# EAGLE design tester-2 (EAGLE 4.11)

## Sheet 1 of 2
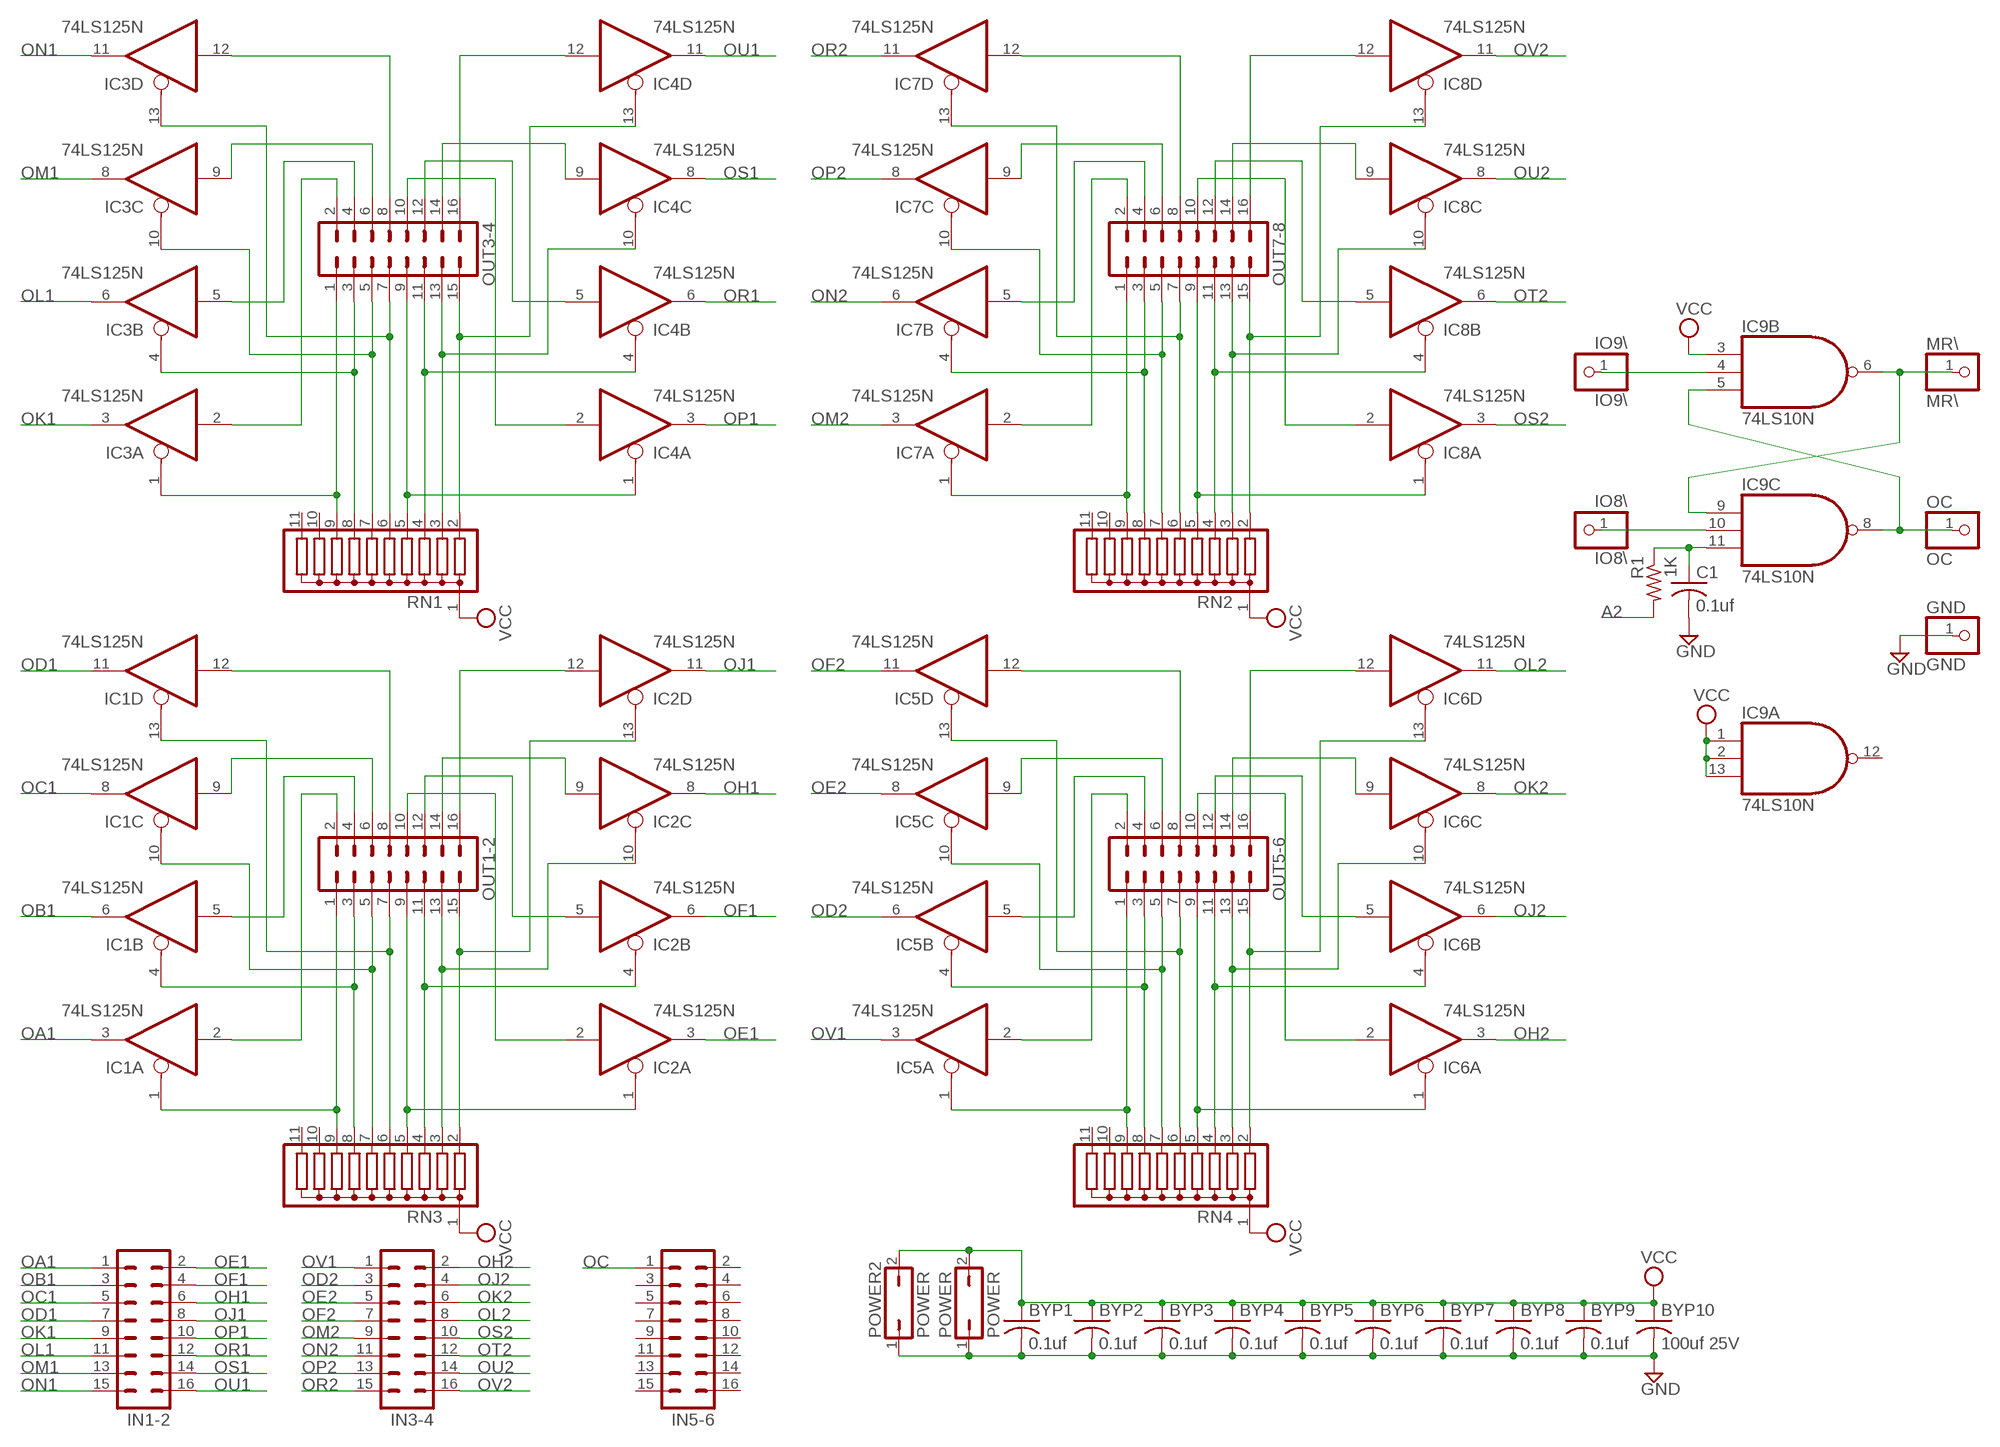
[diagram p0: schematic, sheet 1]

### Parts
BYP1  0.1uf  C-US050-025X075  [C050-025X075]
BYP2  0.1uf  C-US050-025X075  [C050-025X075]
BYP3  0.1uf  C-US050-025X075  [C050-025X075]
BYP4  0.1uf  C-US050-025X075  [C050-025X075]
BYP5  0.1uf  C-US050-025X075  [C050-025X075]
BYP6  0.1uf  C-US050-025X075  [C050-025X075]
BYP7  0.1uf  C-US050-025X075  [C050-025X075]
BYP8  0.1uf  C-US050-025X075  [C050-025X075]
BYP9  0.1uf  C-US050-025X075  [C050-025X075]
BYP10  100uf 25V  C-US150-064X183  [C150-064X183]
C1  0.1uf  C-US050-025X075  [C050-025X075]
GND  GND  PINHD-1X1  [1X01]
IC1  74LS125N  [DIL14]
IC2  74LS125N  [DIL14]
IC3  74LS125N  [DIL14]
IC4  74LS125N  [DIL14]
IC5  74LS125N  [DIL14]
IC6  74LS125N  [DIL14]
IC7  74LS125N  [DIL14]
IC8  74LS125N  [DIL14]
IC9  74LS10N  [DIL14]
IN1-2  MA08-2  [MA08-2]
IN3-4  MA08-2  [MA08-2]
IN5-6  MA08-2  [MA08-2]
IO8\  IO8\  PINHD-1X1  [1X01]
IO9\  IO9\  PINHD-1X1  [1X01]
MR\  MR\  PINHD-1X1  [1X01]
OC  OC  PINHD-1X1  [1X01]
OUT1-2  MA08-2  [MA08-2]
OUT3-4  MA08-2  [MA08-2]
OUT5-6  MA08-2  [MA08-2]
OUT7-8  MA08-2  [MA08-2]
POWER  POWER  JP1Q  [JP1]
POWER2  POWER  JP1Q  [JP1]
R1  1K  R-US_0207/10  [0207/10]
RN1  G10R  [SIL11]
RN2  G10R  [SIL11]
RN3  G10R  [SIL11]
RN4  G10R  [SIL11]

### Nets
A2: R1.2 ; also sheet 2
GND [Power]: BYP1.2 BYP2.2 BYP3.2 BYP4.2 BYP5.2 BYP6.2 BYP7.2 BYP8.2 BYP9.2 BYP10.2 C1.2 GND.1 POWER2.1 POWER.1 ; also sheet 2
IO8\: IC9.10(C:I1) IO8\.1
IO9\: IC9.4(B:I1) IO9\.1
MR\: IC9.6(B:O) IC9.9(C:I0) MR\.1
N$5: C1.1 IC9.11(C:I2) R1.1
N$53: IC1.1(A:OE) OUT1-2.1 RN3.9
N$54: IC1.4(B:OE) OUT1-2.3 RN3.8
N$55: IC1.10(C:OE) OUT1-2.5 RN3.7
N$56: IC1.13(D:OE) OUT1-2.7 RN3.6
N$57: IC1.2(A:I) OUT1-2.2
N$58: IC1.5(B:I) OUT1-2.4
N$59: IC1.9(C:I) OUT1-2.6
N$60: IC1.12(D:I) OUT1-2.8
N$61: IC5.4(B:OE) OUT5-6.3 RN4.8
N$62: IC2.10(C:OE) OUT1-2.13 RN3.3
N$63: IC2.4(B:OE) OUT1-2.11 RN3.4
N$64: IC2.1(A:OE) OUT1-2.9 RN3.5
N$65: IC2.2(A:I) OUT1-2.10
N$66: IC2.5(B:I) OUT1-2.12
N$67: IC2.9(C:I) OUT1-2.14
N$68: IC2.12(D:I) OUT1-2.16
N$138: IC5.13(D:OE) OUT5-6.7 RN4.6
N$139: IC2.13(D:OE) OUT1-2.15 RN3.2
N$140: IC5.2(A:I) OUT5-6.2
N$141: IC5.5(B:I) OUT5-6.4
N$142: IC5.9(C:I) OUT5-6.6
N$143: IC5.12(D:I) OUT5-6.8
N$144: IC6.10(C:OE) OUT5-6.13 RN4.3
N$145: IC6.4(B:OE) OUT5-6.11 RN4.4
N$146: IC6.1(A:OE) OUT5-6.9 RN4.5
N$147: IC6.2(A:I) OUT5-6.10
N$148: IC6.9(C:I) OUT5-6.14
N$149: IC6.12(D:I) OUT5-6.16
N$150: IC5.1(A:OE) OUT5-6.1 RN4.9
N$151: IC5.10(C:OE) OUT5-6.5 RN4.7
N$152: IC6.5(B:I) OUT5-6.12
N$153: IC6.13(D:OE) OUT5-6.15 RN4.2
N$154: IC3.4(B:OE) OUT3-4.3 RN1.8
N$155: IC3.13(D:OE) OUT3-4.7 RN1.6
N$156: IC3.2(A:I) OUT3-4.2
N$157: IC3.5(B:I) OUT3-4.4
N$158: IC3.9(C:I) OUT3-4.6
N$159: IC3.12(D:I) OUT3-4.8
N$160: IC4.10(C:OE) OUT3-4.13 RN1.3
N$161: IC4.4(B:OE) OUT3-4.11 RN1.4
N$162: IC4.1(A:OE) OUT3-4.9 RN1.5
N$163: IC4.2(A:I) OUT3-4.10
N$164: IC4.9(C:I) OUT3-4.14
N$165: IC4.12(D:I) OUT3-4.16
N$166: IC3.1(A:OE) OUT3-4.1 RN1.9
N$167: IC3.10(C:OE) OUT3-4.5 RN1.7
N$168: IC4.5(B:I) OUT3-4.12
N$169: IC4.13(D:OE) OUT3-4.15 RN1.2
N$170: IC7.4(B:OE) OUT7-8.3 RN2.8
N$171: IC7.13(D:OE) OUT7-8.7 RN2.6
N$172: IC7.2(A:I) OUT7-8.2
N$173: IC7.5(B:I) OUT7-8.4
N$174: IC7.9(C:I) OUT7-8.6
N$175: IC7.12(D:I) OUT7-8.8
N$176: IC8.10(C:OE) OUT7-8.13 RN2.3
N$177: IC8.4(B:OE) OUT7-8.11 RN2.4
N$178: IC8.1(A:OE) OUT7-8.9 RN2.5
N$179: IC8.2(A:I) OUT7-8.10
N$180: IC8.9(C:I) OUT7-8.14
N$181: IC8.12(D:I) OUT7-8.16
N$182: IC7.1(A:OE) OUT7-8.1 RN2.9
N$183: IC7.10(C:OE) OUT7-8.5 RN2.7
N$184: IC8.5(B:I) OUT7-8.12
N$185: IC8.13(D:OE) OUT7-8.15 RN2.2
OA1: IC1.3(A:O) IN1-2.1 ; also sheet 2
OB1: IC1.6(B:O) IN1-2.3 ; also sheet 2
OC: IC9.5(B:I2) IC9.8(C:O) IN5-6.1 OC.1
OC1: IC1.8(C:O) IN1-2.5 ; also sheet 2
OD1: IC1.11(D:O) IN1-2.7 ; also sheet 2
OD2: IC5.6(B:O) IN3-4.3 ; also sheet 2
OE1: IC2.3(A:O) IN1-2.2 ; also sheet 2
OE2: IC5.8(C:O) IN3-4.5 ; also sheet 2
OF1: IC2.6(B:O) IN1-2.4 ; also sheet 2
OF2: IC5.11(D:O) IN3-4.7 ; also sheet 2
OH1: IC2.8(C:O) IN1-2.6 ; also sheet 2
OH2: IC6.3(A:O) IN3-4.2 ; also sheet 2
OJ1: IC2.11(D:O) IN1-2.8 ; also sheet 2
OJ2: IC6.6(B:O) IN3-4.4 ; also sheet 2
OK1: IC3.3(A:O) IN1-2.9 ; also sheet 2
OK2: IC6.8(C:O) IN3-4.6 ; also sheet 2
OL1: IC3.6(B:O) IN1-2.11 ; also sheet 2
OL2: IC6.11(D:O) IN3-4.8 ; also sheet 2
OM1: IC3.8(C:O) IN1-2.13 ; also sheet 2
OM2: IC7.3(A:O) IN3-4.9 ; also sheet 2
ON1: IC3.11(D:O) IN1-2.15 ; also sheet 2
ON2: IC7.6(B:O) IN3-4.11 ; also sheet 2
OP1: IC4.3(A:O) IN1-2.10 ; also sheet 2
OP2: IC7.8(C:O) IN3-4.13 ; also sheet 2
OR1: IC4.6(B:O) IN1-2.12 ; also sheet 2
OR2: IC7.11(D:O) IN3-4.15 ; also sheet 2
OS1: IC4.8(C:O) IN1-2.14 ; also sheet 2
OS2: IC8.3(A:O) IN3-4.10 ; also sheet 2
OT2: IC8.6(B:O) IN3-4.12 ; also sheet 2
OU1: IC4.11(D:O) IN1-2.16 ; also sheet 2
OU2: IC8.8(C:O) IN3-4.14 ; also sheet 2
OV1: IC5.3(A:O) IN3-4.1 ; also sheet 2
OV2: IC8.11(D:O) IN3-4.16 ; also sheet 2
VCC [Power]: BYP1.1 BYP2.1 BYP3.1 BYP4.1 BYP5.1 BYP6.1 BYP7.1 BYP8.1 BYP9.1 BYP10.1 IC9.1(A:I0) IC9.2(A:I1) IC9.3(B:I0) IC9.13(A:I2) POWER2.2 POWER.2 RN1.1 RN2.1 RN3.1 RN4.1 ; also sheet 2
Unconnected: IC9.12(A:O) IN5-6.2 IN5-6.3 IN5-6.4 IN5-6.5 IN5-6.6 IN5-6.7 IN5-6.8 IN5-6.9 IN5-6.10 IN5-6.11 IN5-6.12 IN5-6.13 IN5-6.14 IN5-6.15 IN5-6.16 RN1.10 RN1.11 RN2.10 RN2.11 RN3.10 RN3.11 RN4.10 RN4.11

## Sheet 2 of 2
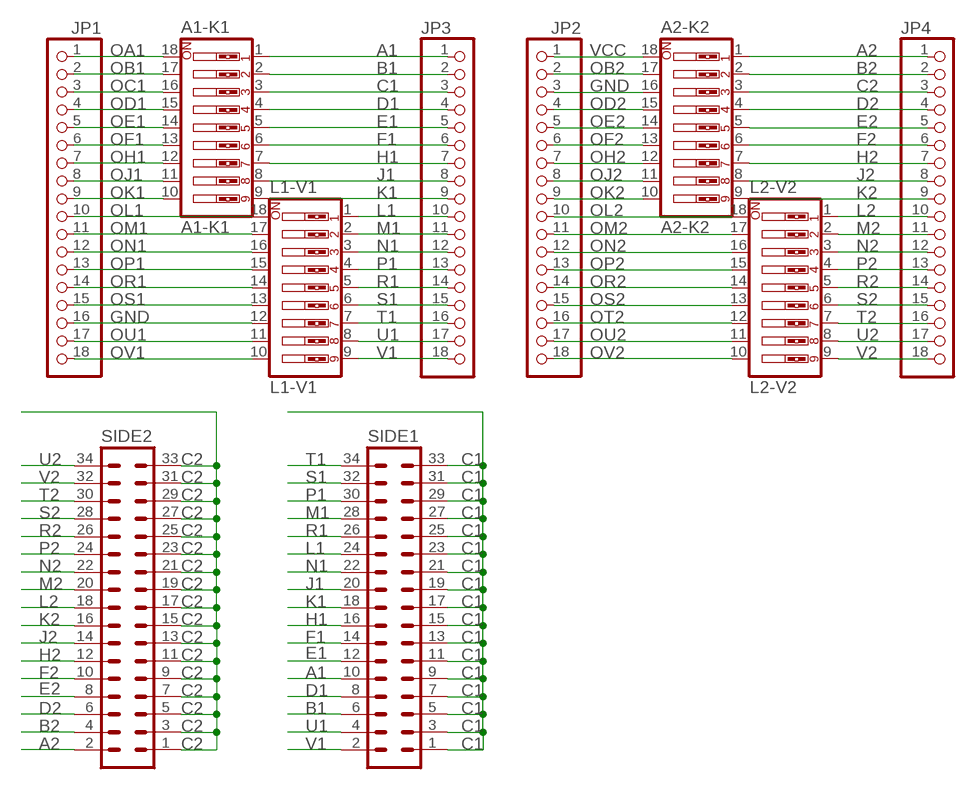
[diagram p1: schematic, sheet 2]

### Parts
A1-K1  A1-K1  SW_DIP-9  [EDG-09]
A2-K2  A2-K2  SW_DIP-9  [EDG-09]
JP1  PINHD-1X18  [1X18]
JP2  PINHD-1X18  [1X18]
JP3  PINHD-1X18  [1X18]
JP4  PINHD-1X18  [1X18]
L1-V1  L1-V1  SW_DIP-9  [EDG-09]
L2-V2  L2-V2  SW_DIP-9  [EDG-09]
SIDE1  MA17-2  [MA17-2]
SIDE2  MA17-2  [MA17-2]

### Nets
A1: A1-K1.1 JP3.1 SIDE1.10
A2: A2-K2.1 JP4.1 SIDE2.2 ; also sheet 1
B1: A1-K1.2 JP3.2 SIDE1.6
B2: A2-K2.2 JP4.2 SIDE2.4
C1: A1-K1.3 JP3.3 SIDE1.1 SIDE1.3 SIDE1.5 SIDE1.7 SIDE1.9 SIDE1.11 SIDE1.13 SIDE1.15 SIDE1.17 SIDE1.19 SIDE1.21 SIDE1.23 SIDE1.25 SIDE1.27 SIDE1.29 SIDE1.31 SIDE1.33
C2: A2-K2.3 JP4.3 SIDE2.1 SIDE2.3 SIDE2.5 SIDE2.7 SIDE2.9 SIDE2.11 SIDE2.13 SIDE2.15 SIDE2.17 SIDE2.19 SIDE2.21 SIDE2.23 SIDE2.25 SIDE2.27 SIDE2.29 SIDE2.31 SIDE2.33
D1: A1-K1.4 JP3.4 SIDE1.8
D2: A2-K2.4 JP4.4 SIDE2.6
E1: A1-K1.5 JP3.5 SIDE1.12
E2: A2-K2.5 JP4.5 SIDE2.8
F1: A1-K1.6 JP3.6 SIDE1.14
F2: A2-K2.6 JP4.6 SIDE2.10
GND [Power]: A2-K2.16 JP1.16 JP2.3 L1-V1.12 ; also sheet 1
H1: A1-K1.7 JP3.7 SIDE1.16
H2: A2-K2.7 JP4.7 SIDE2.12
J1: A1-K1.8 JP3.8 SIDE1.20
J2: A2-K2.8 JP4.8 SIDE2.14
K1: A1-K1.9 JP3.9 SIDE1.18
K2: A2-K2.9 JP4.9 SIDE2.16
L1: JP3.10 L1-V1.1 SIDE1.24
L2: JP4.10 L2-V2.1 SIDE2.18
M1: JP3.11 L1-V1.2 SIDE1.28
M2: JP4.11 L2-V2.2 SIDE2.20
N1: JP3.12 L1-V1.3 SIDE1.22
N2: JP4.12 L2-V2.3 SIDE2.22
OA1: A1-K1.18 JP1.1 ; also sheet 1
OB1: A1-K1.17 JP1.2 ; also sheet 1
OB2: A2-K2.17 JP2.2
OC1: A1-K1.16 JP1.3 ; also sheet 1
OD1: A1-K1.15 JP1.4 ; also sheet 1
OD2: A2-K2.15 JP2.4 ; also sheet 1
OE1: A1-K1.14 JP1.5 ; also sheet 1
OE2: A2-K2.14 JP2.5 ; also sheet 1
OF1: A1-K1.13 JP1.6 ; also sheet 1
OF2: A2-K2.13 JP2.6 ; also sheet 1
OH1: A1-K1.12 JP1.7 ; also sheet 1
OH2: A2-K2.12 JP2.7 ; also sheet 1
OJ1: A1-K1.11 JP1.8 ; also sheet 1
OJ2: A2-K2.11 JP2.8 ; also sheet 1
OK1: A1-K1.10 JP1.9 ; also sheet 1
OK2: A2-K2.10 JP2.9 ; also sheet 1
OL1: JP1.10 L1-V1.18 ; also sheet 1
OL2: JP2.10 L2-V2.18 ; also sheet 1
OM1: JP1.11 L1-V1.17 ; also sheet 1
OM2: JP2.11 L2-V2.17 ; also sheet 1
ON1: JP1.12 L1-V1.16 ; also sheet 1
ON2: JP2.12 L2-V2.16 ; also sheet 1
OP1: JP1.13 L1-V1.15 ; also sheet 1
OP2: JP2.13 L2-V2.15 ; also sheet 1
OR1: JP1.14 L1-V1.14 ; also sheet 1
OR2: JP2.14 L2-V2.14 ; also sheet 1
OS1: JP1.15 L1-V1.13 ; also sheet 1
OS2: JP2.15 L2-V2.13 ; also sheet 1
OT2: JP2.16 L2-V2.12 ; also sheet 1
OU1: JP1.17 L1-V1.11 ; also sheet 1
OU2: JP2.17 L2-V2.11 ; also sheet 1
OV1: JP1.18 L1-V1.10 ; also sheet 1
OV2: JP2.18 L2-V2.10 ; also sheet 1
P1: JP3.13 L1-V1.4 SIDE1.30
P2: JP4.13 L2-V2.4 SIDE2.24
R1: JP3.14 L1-V1.5 SIDE1.26
R2: JP4.14 L2-V2.5 SIDE2.26
S1: JP3.15 L1-V1.6 SIDE1.32
S2: JP4.15 L2-V2.6 SIDE2.28
T1: JP3.16 L1-V1.7 SIDE1.34
T2: JP4.16 L2-V2.7 SIDE2.30
U1: JP3.17 L1-V1.8 SIDE1.4
U2: JP4.17 L2-V2.8 SIDE2.34
V1: JP3.18 L1-V1.9 SIDE1.2
V2: JP4.18 L2-V2.9 SIDE2.32
VCC [Power]: A2-K2.18 JP2.1 ; also sheet 1

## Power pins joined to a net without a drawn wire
GND: IC1.7(P:GND) IC2.7(P:GND) IC3.7(P:GND) IC4.7(P:GND) IC5.7(P:GND) IC6.7(P:GND) IC7.7(P:GND) IC8.7(P:GND) IC9.7(P:GND)
VCC: IC1.14(P:VCC) IC2.14(P:VCC) IC3.14(P:VCC) IC4.14(P:VCC) IC5.14(P:VCC) IC6.14(P:VCC) IC7.14(P:VCC) IC8.14(P:VCC) IC9.14(P:VCC)

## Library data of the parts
A1-K1 A2-K2 L1-V1 L2-V2 = special:SW_DIP-9: DIP SWITCH
BYP1-BYP10 C1 = rcl:C-US: CAPACITOR, American symbol
GND IO8\ IO9\ MR\ OC = pinhead:PINHD-1X1: PIN HEADER
IC1-IC8 = 74xx-jameco:74*125: Quad bus BUFFER, 3-state
IC9 = 74xx-jameco:74*10: Triple 3-input NAND gate
IN1-2 IN3-4 IN5-6 OUT1-2 OUT3-4 OUT5-6 OUT7-8 = con-lstb:MA08-2: PIN HEADER
JP1-JP4 = pinhead:PINHD-1X18: PIN HEADER
POWER POWER2 = jumper:JP1Q: JUMPER
R1 = rcl:R-US_: RESISTOR, American symbol
RN1-RN4 = resistor-sil:G10R: SIL RESISTOR
SIDE1 SIDE2 = con-lstb:MA17-2: PIN HEADER

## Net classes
1 Power: width 0.305 mm, drill 0.305 mm

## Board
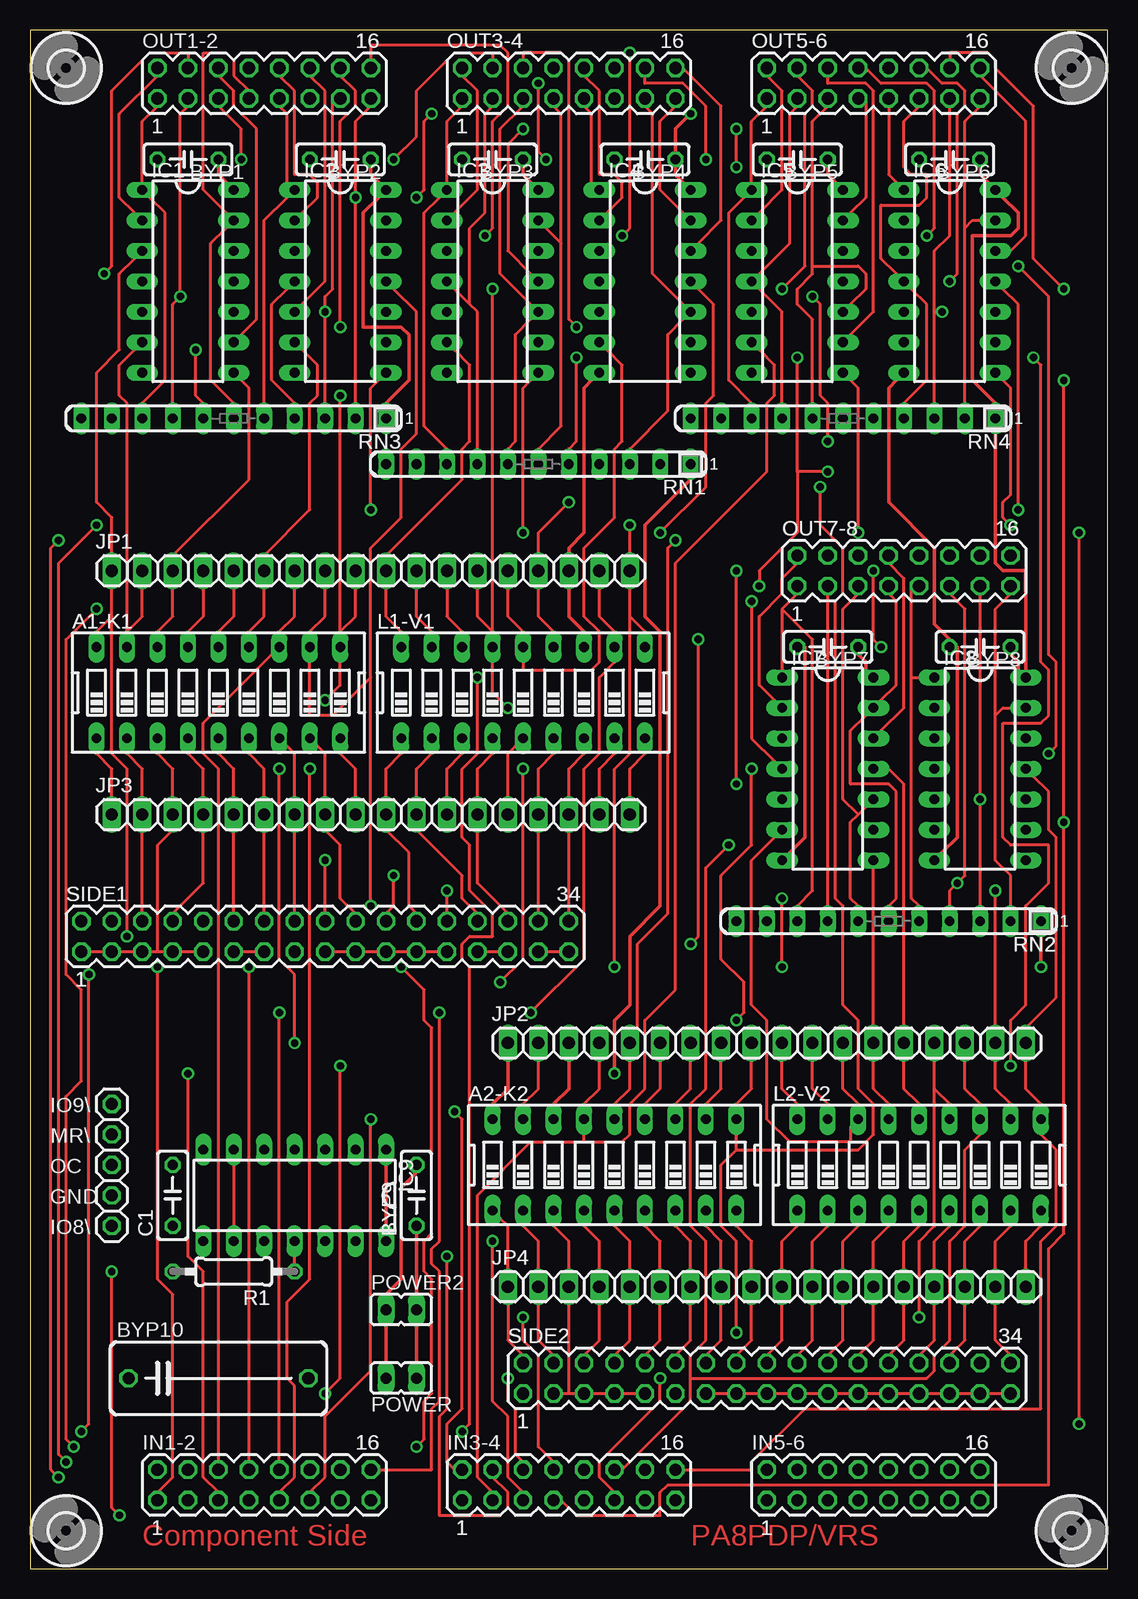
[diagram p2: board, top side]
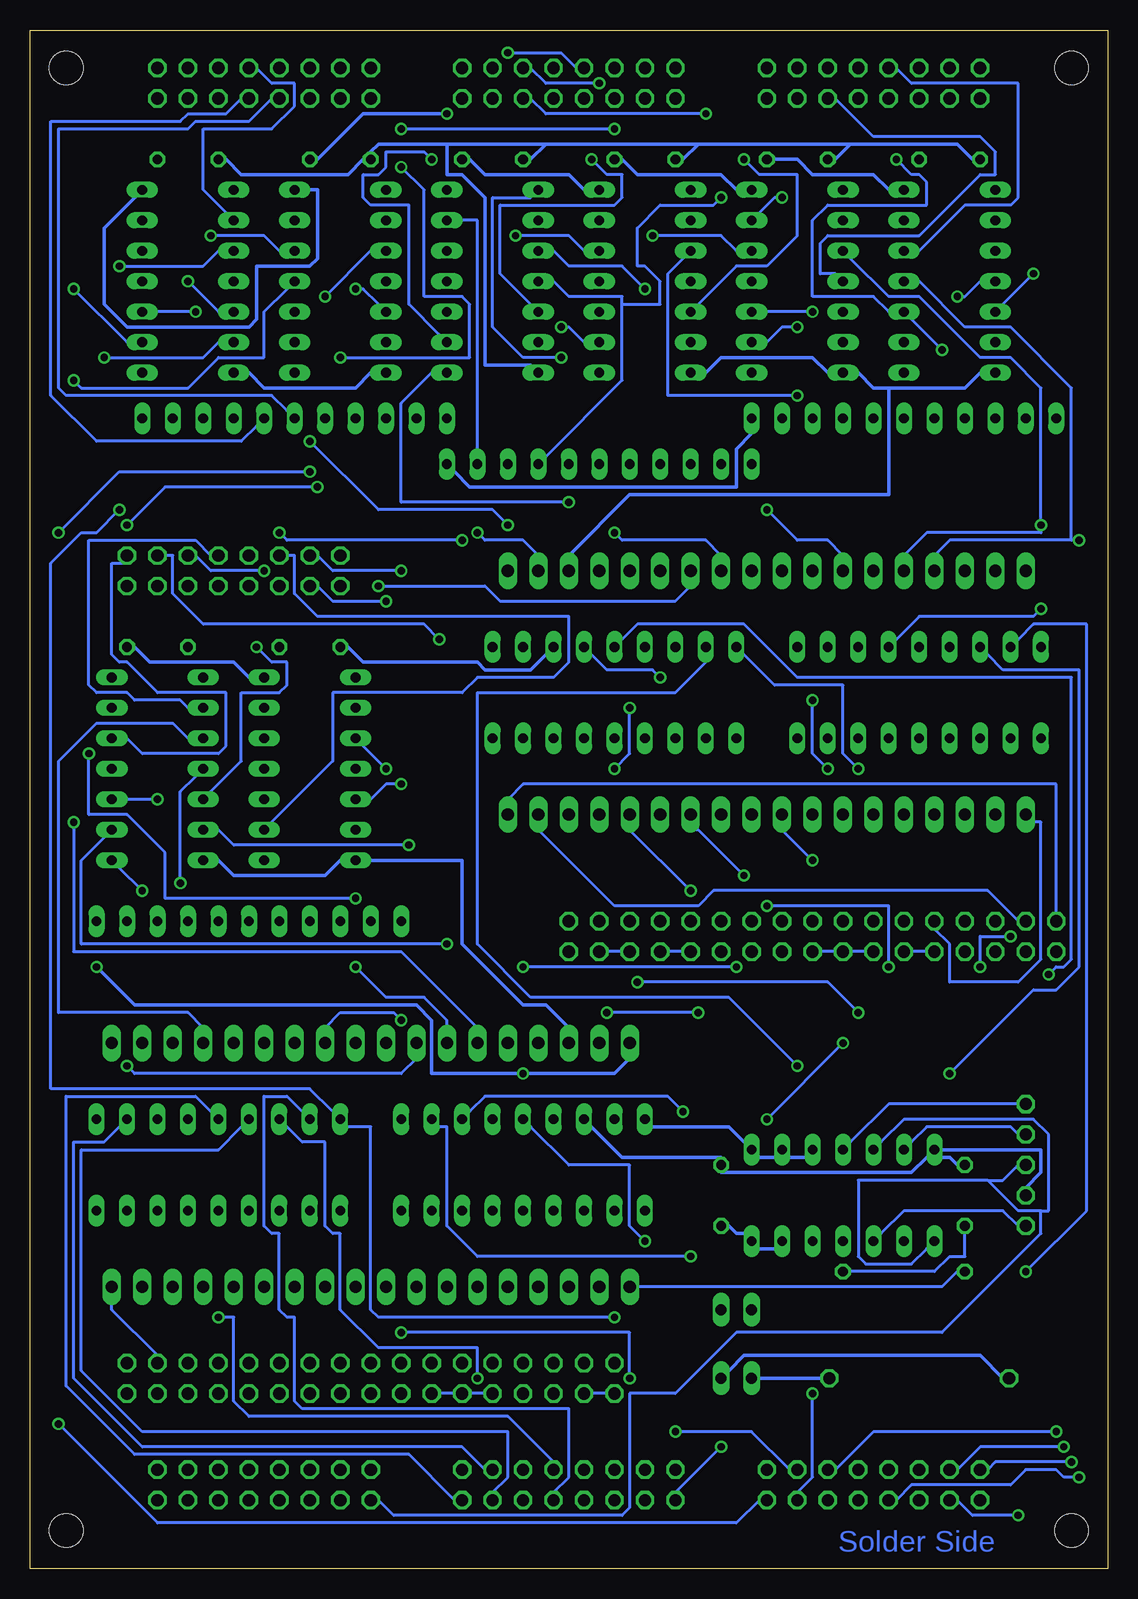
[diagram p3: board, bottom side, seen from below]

Size 89.84 x 128.25 mm. Coordinates in mm from the lower left corner, seen from the top.
Outline: 0,128.25 0,0 89.84,0 89.84,128.25 0,128.25
Copper layers (1*16): Top 0.035mm / dielectric 1.5mm / Bottom 0.035mm
Design rules "custompcb": minimum track width 10mil, minimum drill 24mil, track to track 12mil, track to pad 12mil, pad to pad 12mil, via to via 12mil, smd to smd 12mil, copper to edge 40mil, drill to drill 12mil, minimum pad ring 10mil, minimum via ring 8mil, stop-mask expansion 0mil, vias tented up to drill 0mil, thermal gap 10mil

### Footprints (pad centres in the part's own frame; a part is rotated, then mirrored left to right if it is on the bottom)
EDG-09 = drill 0.813 long: 1 -10.16,-3.81; 2 -7.62,-3.81; 3 -5.08,-3.81; 4 -2.54,-3.81; 5 0,-3.81; 6 2.54,-3.81; 7 5.08,-3.81; 8 7.62,-3.81; 9 10.16,-3.81; 10 10.16,3.81; 11 7.62,3.81; 12 5.08,3.81; 13 2.54,3.81; 14 0,3.81; 15 -2.54,3.81; 16 -5.08,3.81; 17 -7.62,3.81; 18 -10.16,3.81
C050-025X075 = drill 0.813 octagon: 1 -2.54,0; 2 2.54,0
C150-064X183 = drill 1.016 octagon: 1 -7.493,0; 2 7.493,0
1X01 = drill 1.016 octagon: 1 0,0
DIL14 = drill 0.813 long: 1 -7.62,-3.81; 2 -5.08,-3.81; 3 -2.54,-3.81; 4 0,-3.81; 5 2.54,-3.81; 6 5.08,-3.81; 7 7.62,-3.81; 8 7.62,3.81; 9 5.08,3.81; 10 2.54,3.81; 11 0,3.81; 12 -2.54,3.81; 13 -5.08,3.81; 14 -7.62,3.81
MA08-2 = drill 1.016 octagon: 1 -8.89,-1.27; 2 -8.89,1.27; 3 -6.35,-1.27; 4 -6.35,1.27; 5 -3.81,-1.27; 6 -3.81,1.27; 7 -1.27,-1.27; 8 -1.27,1.27; 9 1.27,-1.27; 10 1.27,1.27; 11 3.81,-1.27; 12 3.81,1.27; 13 6.35,-1.27; 14 6.35,1.27; 15 8.89,-1.27; 16 8.89,1.27
1X18 = drill 1.016 long: 1 -21.59,0; 2 -19.05,0; 3 -16.51,0; 4 -13.97,0; 5 -11.43,0; 6 -8.89,0; 7 -6.35,0; 8 -3.81,0; 9 -1.27,0; 10 1.27,0; 11 3.81,0; 12 6.35,0; 13 8.89,0; 14 11.43,0; 15 13.97,0; 16 16.51,0; 17 19.05,0; 18 21.59,0
JP1 = drill 0.914 long: 1 0,-1.27; 2 0,1.27
0207/10 = drill 0.813 octagon: 1 -5.08,0; 2 5.08,0
SIL11 = drill 0.813 long: 1 -12.7,0; 2 -10.16,0; 3 -7.62,0; 4 -5.08,0; 5 -2.54,0; 6 0,0; 7 2.54,0; 8 5.08,0; 9 7.62,0; 10 10.16,0; 11 12.7,0
MA17-2 = drill 1.016 octagon: 1 -20.32,-1.27; 2 -20.32,1.27; 3 -17.78,-1.27; 4 -17.78,1.27; 5 -15.24,-1.27; 6 -15.24,1.27; 7 -12.7,-1.27; 8 -12.7,1.27; 9 -10.16,-1.27; 10 -10.16,1.27; 11 -7.62,-1.27; 12 -7.62,1.27; 13 -5.08,-1.27; 14 -5.08,1.27; 15 -2.54,-1.27; 16 -2.54,1.27; 17 0,-1.27; 18 0,1.27; 19 2.54,-1.27; 20 2.54,1.27; 21 5.08,-1.27; 22 5.08,1.27; 23 7.62,-1.27; 24 7.62,1.27; 25 10.16,-1.27; 26 10.16,1.27; 27 12.7,-1.27; 28 12.7,1.27; 29 15.24,-1.27; 30 15.24,1.27; 31 17.78,-1.27; 32 17.78,1.27; 33 20.32,-1.27; 34 20.32,1.27
2,8 = hole 2.8: 0,0

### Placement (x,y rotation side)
A1-K1  15.71,73.01 0 top
A2-K2  48.73,33.64 0 top
BYP1  13.17,117.46 180 top
BYP2  25.87,117.46 180 top
BYP3  38.57,117.46 180 top
BYP4  51.27,117.46 180 top
BYP5  63.97,117.46 180 top
BYP6  76.67,117.46 180 top
BYP7  66.51,76.82 180 top
BYP8  79.21,76.82 180 top
BYP9  32.22,31.1 90 top
BYP10  15.71,15.86 0 top
C1  11.9,31.1 90 top
GND  6.82,31.1 90 top
IC1  13.17,107.3 270 top
IC2  25.87,107.3 270 top
IC3  38.57,107.3 270 top
IC4  51.27,107.3 270 top
IC5  63.97,107.3 270 top
IC6  76.67,107.3 270 top
IC7  66.51,66.66 270 top
IC8  79.21,66.66 270 top
IC9  22.06,31.1 180 top
IN1-2  19.52,6.97 0 top
IN3-4  44.92,6.97 0 top
IN5-6  70.32,6.97 0 top
IO8\  6.82,28.56 90 top
IO9\  6.82,38.72 90 top
JP1  28.41,83.17 0 top
JP2  61.43,43.8 0 top
JP3  28.41,62.85 0 top
JP4  61.43,23.48 0 top
L1-V1  41.11,73.01 0 top
L2-V2  74.13,33.64 0 top
MR\  6.82,36.18 90 top
OC  6.82,33.64 90 top
OUT1-2  19.52,123.81 0 top
OUT3-4  44.92,123.81 0 top
OUT5-6  70.32,123.81 0 top
OUT7-8  72.86,83.17 0 top
POWER  30.95,15.86 270 top
POWER2  30.95,21.57 270 top
R1  16.98,24.75 180 top
RN1  42.38,92.06 180 top
RN2  71.59,53.96 180 top
RN3  16.98,95.87 180 top
RN4  67.78,95.87 180 top
SIDE1  24.6,52.69 0 top
SIDE2  61.43,15.86 0 top
U$1  [2,8]  3.01,3.16 270 top
U$2  [2,8]  86.83,3.16 270 top
U$3  [2,8]  86.83,125.08 270 top
U$4  [2,8]  3.01,125.08 270 top

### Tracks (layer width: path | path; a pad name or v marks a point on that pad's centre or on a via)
A1
  Top 0.254: A1-K1.1 5.55,67.93 6.82,66.66 6.82,64.12 JP3.1
  Bottom 0.254: SIDE1.10 14.44,53.33 13.17,52.05 13.17,48.88 7.46,48.88 5.55,50.78 5.55,62.21 6.18,62.21 JP3.1
A2
  Top 0.254: A2-K2.1 39.2,29.2 39.84,28.56 39.84,24.75 JP4.1 39.84,22.21 39.84,19.04 41.11,17.77 SIDE2.2
  Bottom 0.254: R1.2 12.54,24.75 13.81,23.48 39.2,23.48 JP4.1
B1
  Top 0.254: A1-K1.2 8.09,67.93 9.36,66.66 9.36,64.12 JP3.2 9.36,61.58 9.36,54.59 SIDE1.6
B2
  Top 0.254: A2-K2.2 41.11,28.56 42.38,27.29 42.38,24.75 JP4.2 42.38,22.21 42.38,19.04 43.65,17.77 SIDE2.4
C1
  Top 0.254: A1-K1.3 10.63,67.93 11.9,66.66 11.9,64.12 JP3.3 11.9,61.58 10.63,60.31 10.63,51.42 | SIDE1.1 4.92,51.42 6.18,51.42 SIDE1.3 7.46,51.42 8.73,51.42 SIDE1.5 10,51.42 10.63,51.42 | 10.63,51.42 11.27,51.42 SIDE1.7 12.54,51.42 13.81,51.42 SIDE1.9 | SIDE1.13 18.89,51.42 17.62,51.42 SIDE1.11 | SIDE1.17 25.23,51.42 26.51,51.42 SIDE1.19 27.78,51.42 29.05,51.42 SIDE1.21 30.32,51.42 31.59,51.42 SIDE1.23 32.86,51.42 34.12,51.42 SIDE1.25 | SIDE1.29 39.2,51.42 37.94,51.42 SIDE1.27 | SIDE1.33 44.29,51.42 43.02,51.42 SIDE1.31
  Bottom 0.254: SIDE1.11 16.35,51.42 15.08,51.42 SIDE1.9 | SIDE1.13 20.16,51.42 21.43,51.42 SIDE1.15 22.7,51.42 23.96,51.42 SIDE1.17 | SIDE1.27 36.66,51.42 35.4,51.42 SIDE1.25 | SIDE1.31 41.74,51.42 40.48,51.42 SIDE1.29
C2
  Top 0.254: A2-K2.3 43.65,28.56 44.92,27.29 44.92,24.75 JP4.3 44.92,22.21 44.92,14.59 | 44.92,14.59 44.29,14.59 SIDE2.3 | 44.92,14.59 45.55,14.59 SIDE2.5 46.83,14.59 48.09,14.59 SIDE2.7 49.37,14.59 50.63,14.59 SIDE2.9 | SIDE2.13 56.98,14.59 58.26,14.59 SIDE2.15 59.52,14.59 60.8,14.59 SIDE2.17 62.06,14.59 63.34,14.59 SIDE2.19 64.6,14.59 65.88,14.59 SIDE2.21 67.14,14.59 68.41,14.59 SIDE2.23 69.68,14.59 70.95,14.59 SIDE2.25 72.22,14.59 73.49,14.59 SIDE2.27 74.77,14.59 76.03,14.59 SIDE2.29 77.3,14.59 78.57,14.59 SIDE2.31 79.84,14.59 81.11,14.59 SIDE2.33
  Bottom 0.254: SIDE2.1 41.74,14.59 43.02,14.59 SIDE2.3 | SIDE2.9 51.91,14.59 53.18,14.59 SIDE2.11 54.45,14.59 55.72,14.59 SIDE2.13
D1
  Top 0.254: A1-K1.4 13.17,67.93 14.44,66.66 14.44,64.12 JP3.4 14.44,61.58 14.44,57.13 11.9,54.59 SIDE1.8
D2
  Top 0.254: A2-K2.4 46.19,28.56 47.46,27.29 47.46,24.75 JP4.4 47.46,22.21 47.46,19.04 46.19,17.77 SIDE2.6
E1
  Top 0.254: A1-K1.5 15.71,67.93 16.98,66.66 16.98,64.12 JP3.5 16.98,61.58 16.98,54.59 SIDE1.12
E2
  Top 0.254: A2-K2.5 48.73,28.56 50,27.29 50,24.75 JP4.5 50,22.21 50,19.04 48.73,17.77 SIDE2.8
F1
  Top 0.254: A1-K1.6 18.25,67.93 19.52,66.66 19.52,64.12 JP3.6 19.52,61.58 19.52,54.59 SIDE1.14
F2
  Top 0.254: A2-K2.6 51.27,28.56 52.54,27.29 52.54,24.75 JP4.6 52.54,22.21 52.54,19.04 51.27,17.77 SIDE2.10
GND
  Top 0.305: A2-K2.16 43.65,38.72 44.92,39.99 44.92,42.53 JP2.3 | BYP9.2 32.22,33.01 30.95,31.73 30.95,24.11 29.68,22.84 POWER2.1 29.68,20.3 29.68,17.13 POWER.1 | IC7.7 63.34,59.67 64.6,60.95 64.6,76.82 BYP7.2 | IC8.7 76.03,59.67 77.3,60.95 77.3,76.82 BYP8.2 76.67,77.45 75.4,78.72 75.4,85.08 71.59,88.89 71.59,98.41 72.22,99.05 IC6.7 | L1-V1.12 46.19,78.09 44.92,79.36 44.92,81.9 JP1.16 44.92,84.44 44.92,85.08 46.19,86.34 46.19,98.41 46.83,99.05 IC4.7
  Bottom 0.305: C1.2 12.54,33.64 13.17,34.27 13.81,34.27 IC9.7 | GND.1 6.82,31.73 5.55,33.01 5.55,34.91 13.81,34.91 IC9.7 | BYP10.2 23.33,15.86 29.05,15.86 POWER.1 | A2-K2.16 43.02,36.81 40.48,34.27 32.22,34.27 BYP9.2 32.22,33.01 16.35,33.01 15.08,34.27 IC9.7 | 21.43,118.73 12.54,118.73 11.27,117.46 BYP1.2 | 21.43,118.73 22.7,117.46 BYP2.2 | 34.12,118.73 35.4,117.46 BYP3.2 | 34.12,118.73 21.43,118.73 | 46.83,118.73 48.09,117.46 BYP4.2 | 46.83,118.73 34.12,118.73 | 55.08,118.73 46.83,118.73 | 55.08,118.73 60.8,118.73 61.43,118.09 BYP5.2 62.06,117.46 63.34,116.19 72.22,116.19 73.49,117.46 BYP6.2 | IC5.7 61.43,99.68 62.7,98.41 70.32,98.41 71.59,99.68 IC6.7 | IC8.7 74.13,59.04 72.86,57.77 65.24,57.77 63.97,59.04 IC7.7 61.43,59.04 53.81,59.04 53.81,52.05 48.73,46.98 46.83,46.98 44.92,45.07 JP2.3 | 18.25,98.41 19.52,98.41 20.79,99.68 IC2.7 23.33,99.68 24.6,100.95 32.22,100.95 33.49,99.68 IC3.7 | 18.25,98.41 11.9,98.41 10.63,99.68 IC1.7 | 18.25,98.41 18.25,89.52 39.84,89.52 44.92,84.44 JP1.16 | BYP7.2 63.34,76.82 62.06,75.55 52.54,75.55 51.91,74.92 48.09,74.92 46.83,76.19 L1-V1.12 | 55.08,118.73 55.08,116.19 53.81,116.19 51.91,114.28 51.91,100.31 48.09,100.31 IC4.7
H1
  Top 0.254: A1-K1.7 21.43,68.56 22.06,67.93 22.06,64.12 JP3.7 22.06,61.58 22.06,54.59 SIDE1.16
H2
  Top 0.254: A2-K2.7 53.81,28.56 55.08,27.29 55.08,24.75 JP4.7 55.08,22.21 55.08,19.04 53.81,17.77 SIDE2.12
IO8\
  Bottom 0.254: IC9.10 18.89,27.93 16.98,29.83 8.73,29.83 7.46,28.56 IO8\.1
IO9\
  Bottom 0.254: IC9.4 21.43,35.55 18.25,38.72 7.46,38.72 IO9\.1
J1
  Top 0.254: A1-K1.8 23.96,68.56 24.6,67.93 24.6,64.12 JP3.8 24.6,61.58 25.87,60.31 25.87,55.87 27.14,54.59 SIDE1.20
J2
  Top 0.254: A2-K2.8 56.35,28.56 57.62,27.29 57.62,24.75 JP4.8 57.62,22.21 57.62,19.04 56.35,17.77 SIDE2.14
K1  (via drill 0.61)
  Top 0.254: A1-K1.9 25.87,67.93 27.14,66.66 27.14,64.12 JP3.9 | v24.6,59.04 24.6,54.59 SIDE1.18
  Bottom 0.254: v24.6,59.04 27.14,61.58 JP3.9
K2
  Top 0.254: A2-K2.9 58.89,28.56 60.16,27.29 60.16,24.75 JP4.9 60.16,22.21 60.16,19.04 58.89,17.77 SIDE2.16
L1
  Top 0.254: L1-V1.1 30.95,67.93 29.68,66.66 29.68,64.12 JP3.10 29.68,61.58 31.59,59.67 31.59,55.23 32.22,54.59 SIDE1.24
L2
  Top 0.254: L2-V2.1 63.97,28.56 62.7,27.29 62.7,24.75 JP4.10 62.7,22.21 62.7,19.04 61.43,17.77 SIDE2.18
M1
  Top 0.254: L1-V1.2 33.49,67.93 32.22,66.66 32.22,64.12 JP3.11 32.22,61.58 36.03,57.77 36.03,55.87 37.3,54.59 SIDE1.28
M2
  Top 0.254: L2-V2.2 66.51,28.56 65.24,27.29 65.24,24.75 JP4.11 65.24,22.21 65.24,19.04 63.97,17.77 SIDE2.20
MR\
  Top 0.254: IC9.9 16.98,28.56 16.98,33.64 IC9.6
  Bottom 0.254: MR\.1 7.46,36.18 8.09,36.81 15.08,36.81 16.35,35.55 IC9.6
N1  (via drill 0.61)
  Top 0.254: L1-V1.3 36.03,67.93 34.76,66.66 34.76,64.12 JP3.12 | v30.32,57.77 30.32,55.23 29.68,54.59 SIDE1.22
  Bottom 0.254: v30.32,57.77 34.12,61.58 34.76,61.58 JP3.12
N2
  Top 0.254: L2-V2.3 69.05,28.56 67.78,27.29 67.78,24.75 JP4.12 67.78,22.21 67.78,19.04 66.51,17.77 SIDE2.22
N$5
  Top 0.254: R1.1 22.06,25.38 22.06,26.02 IC9.11
  Bottom 0.254: C1.1 11.9,27.93 11.9,26.02 13.17,26.02 14.44,24.75 21.43,24.75 R1.1
N$53
  Top 0.254: RN3.9 9.36,97.14 11.27,99.05 11.27,113.02 10,114.28 IC1.1 9.36,115.55 9.36,120.64 10.63,121.91 OUT1-2.1
N$54  (via drill 0.61)
  Top 0.254: RN3.8 11.9,97.14 11.9,105.39 v12.54,106.03 12.54,121.27 13.17,121.91 OUT1-2.3
  Bottom 0.254: v12.54,106.03 11.9,106.03 10.63,107.3 IC1.4
N$55  (via drill 0.61)
  Top 0.254: v13.81,101.58 13.81,97.78 14.44,97.14 RN3.7 | v17.62,117.46 17.62,120 15.71,121.91 OUT1-2.5
  Bottom 0.254: v13.81,101.58 16.35,104.12 IC1.10 18.25,104.76 19.52,106.03 24.6,106.03 24.6,112.38 23.33,113.65 15.08,113.65 15.08,115.55 15.71,116.19 16.35,116.19 v17.62,117.46
N$56
  Top 0.254: RN3.6 16.98,97.14 15.08,99.05 15.08,110.47 16.35,111.75 IC1.13 16.35,113.02 14.44,114.92 14.44,126.35 16.35,126.35 16.98,125.72 16.98,124.44 18.25,123.17 OUT1-2.7
N$57
  Top 0.254: IC1.2 8.73,113.02 7.46,114.28 7.46,121.27 10.63,124.44 OUT1-2.2
N$58  (via drill 0.61)
  Top 0.254: v6.18,107.94 6.82,108.57 6.82,123.17 10,126.35 13.17,126.35 13.17,125.72 OUT1-2.4
  Bottom 0.254: v6.18,107.94 8.73,105.39 IC1.5
N$59
  Top 0.254: IC1.9 17.62,102.86 18.89,104.12 18.89,120 16.98,121.91 16.98,123.17 15.71,124.44 OUT1-2.6
N$60
  Bottom 0.254: IC1.12 15.71,109.84 11.9,113.65 8.09,113.65 7.46,114.28 7.46,123.81 16.35,123.81 17.62,125.08 OUT1-2.8
N$61
  Top 0.254: RN4.8 62.7,97.14 62.7,104.76 60.8,106.67 IC5.4 60.8,107.94 63.34,110.47 63.34,121.27 63.97,121.91 OUT5-6.3
N$62  (via drill 0.61)
  Top 0.254: RN3.3 24.6,97.14 v24.6,104.76 24.6,106.03 25.23,106.67 25.23,122.54 OUT1-2.13
  Bottom 0.254: v24.6,104.76 28.41,104.76 IC2.10
N$63
  Top 0.254: RN3.4 22.06,97.14 20.16,99.05 20.16,105.39 21.43,106.67 IC2.4
  Bottom 0.254: OUT1-2.11 22.7,122.54 19.52,119.36 10.63,119.36 9.36,118.09 9.36,116.19 10.63,116.19 15.71,111.11 23.33,111.11 23.96,110.47 23.96,107.94 22.7,107.94 IC2.4
N$64
  Top 0.254: RN3.5 19.52,97.14 19.52,112.38 21.43,114.28 IC2.1 21.43,115.55 21.43,121.27 20.79,121.91 OUT1-2.9
N$65
  Top 0.254: IC2.2 22.7,113.02 23.96,114.28 23.96,115.55 23.33,116.19 22.06,116.19 22.06,123.17 20.79,124.44 OUT1-2.10
N$66
  Top 0.254: IC2.5 22.7,105.39 24.6,107.3 24.6,123.17 23.33,124.44 OUT1-2.12
N$67  (via drill 0.61)
  Top 0.254: v25.87,103.49 25.87,120.64 27.14,121.91 27.14,123.17 25.87,124.44 OUT1-2.14
  Bottom 0.254: v25.87,103.49 27.14,103.49 28.41,102.22 IC2.9
N$68  (via drill 0.61)
  Top 0.254: v37.94,111.11 38.57,111.75 38.57,120.64 39.84,121.91 39.84,126.35 39.2,126.98 28.41,126.98 28.41,125.72 OUT1-2.16
  Bottom 0.254: v37.94,111.11 32.22,111.11 30.95,109.84 IC2.12
N$138
  Top 0.254: IC5.13 68.41,113.02 69.68,114.28 69.68,122.54 OUT5-6.7
  Bottom 0.254: RN4.6 68.41,96.5 69.68,97.78 86.83,97.78 87.46,98.41 87.46,120 76.67,120 76.03,120.64 71.59,120.64 69.68,122.54 OUT5-6.7
N$139  (via drill 0.61)
  Top 0.254: RN3.2 27.14,97.14 v27.14,114.28 27.14,120.64 28.41,121.91 OUT1-2.15
  Bottom 0.254: v27.14,114.28 27.78,114.28 29.05,113.02 IC2.13
N$140
  Top 0.254: IC5.2 60.8,113.02 62.7,114.92 62.7,123.17 61.43,124.44 OUT5-6.2
N$141  (via drill 0.61)
  Top 0.254: v62.7,106.67 64.6,108.57 64.6,121.27 65.24,121.91 65.24,123.17 63.97,124.44 OUT5-6.4
  Bottom 0.254: v62.7,106.67 62.06,106.67 60.8,105.39 IC5.5
N$142
  Top 0.254: IC5.9 68.41,102.86 70.32,104.76 70.32,123.17 69.68,123.81 66.51,123.81 66.51,124.44 OUT5-6.6
N$143  (via drill 0.61)
  Top 0.254: v74.77,111.11 75.4,111.75 75.4,123.17 74.77,123.81 70.95,123.81 69.68,125.08 OUT5-6.8
  Bottom 0.254: v74.77,111.11 70.32,111.11 69.05,109.84 IC5.12
N$144  (via drill 0.61)
  Top 0.254: 75.4,104.76 75.4,109.84 76.67,111.11 76.67,121.91 OUT5-6.13 | 75.4,104.76 75.4,97.14 RN4.3 | 75.4,104.76 v76.03,104.76
  Bottom 0.254: v76.03,104.76 79.21,104.76 IC6.10
N$145
  Top 0.254: RN4.4 72.86,97.14 74.77,99.05 74.77,105.39 73.49,106.67 IC6.4 72.22,107.94 70.95,109.2 70.95,113.65 74.13,113.65 74.77,114.28 74.77,116.19 73.49,116.19 72.86,116.83 72.86,120.64 74.13,121.91 OUT5-6.11
N$146
  Top 0.254: IC6.1 72.22,115.55 71.59,116.19 71.59,121.91 OUT5-6.9
  Bottom 0.254: RN4.5 70.95,95.23 72.22,93.97 84.29,93.97 88.1,97.78 88.1,120.64 77.3,120.64 76.67,121.27 73.49,121.27 72.22,122.54 OUT5-6.9
N$147
  Bottom 0.254: IC6.2 73.49,113.02 75.4,114.92 75.4,120 69.68,120 67.78,121.91 67.78,123.81 69.68,123.81 70.95,125.08 OUT5-6.10
N$148  (via drill 0.61)
  Top 0.254: v86.19,106.67 83.65,109.2 83.65,121.91 80.48,125.08 80.48,125.72 79.84,126.35 76.67,126.35 76.67,125.72 OUT5-6.14
  Bottom 0.254: v86.19,106.67 81.75,102.22 IC6.9
N$149
  Top 0.254: IC6.12 81.75,109.84 83.02,111.11 83.02,120.64 79.21,124.44 OUT5-6.16
N$150
  Top 0.254: RN4.9 60.16,97.14 58.26,99.05 58.26,113.02 59.52,114.28 IC5.1 60.16,115.55 60.16,120.64 61.43,121.91 OUT5-6.1
N$151
  Top 0.254: 65.24,108.57 65.24,120.64 66.51,121.91 OUT5-6.5 | 65.24,108.57 65.24,107.94 63.97,106.67 63.97,105.39 65.24,104.12 65.24,97.14 RN4.7 | 65.24,108.57 69.05,108.57 69.68,107.94 69.68,106.67 68.41,105.39 IC5.10
N$152  (via drill 0.61)
  Top 0.254: v76.67,107.3 77.3,107.94 77.3,121.27 77.94,121.91 77.94,123.17 77.3,123.81 76.03,123.81 74.77,125.08 OUT5-6.12
  Bottom 0.254: v76.67,107.3 74.13,104.76 IC6.5
N$153
  Top 0.254: 77.94,111.75 77.94,97.14 RN4.2 | 77.94,111.75 78.57,112.38 79.21,112.38 IC6.13 | 77.94,111.75 77.94,120.64 79.21,121.91 OUT5-6.15
N$154
  Top 0.254: 36.66,105.39 35.4,106.67 IC3.4 | 36.66,105.39 37.3,104.76 37.3,93.33 RN1.8 | 36.66,105.39 36.66,111.75 37.94,113.02 37.94,121.27 38.57,121.91 OUT3-4.3
N$155
  Top 0.254: 44.29,110.47 44.29,95.23 42.38,93.33 RN1.6 | 44.29,110.47 43.02,111.75 IC3.13 | 44.29,110.47 44.29,121.27 43.65,121.91 OUT3-4.7
N$156
  Top 0.254: IC3.2 35.4,113.02 37.3,114.92 37.3,123.17 36.03,124.44 OUT3-4.2
N$157  (via drill 0.61)
  Top 0.254: v30.32,117.46 32.22,119.36 32.22,123.17 35.4,126.35 38.57,126.35 38.57,125.72 OUT3-4.4
  Bottom 0.254: v30.32,117.46 29.05,116.19 25.87,116.19 25.87,111.11 28.41,108.57 30.95,108.57 34.12,105.39 IC3.5
N$158  (via drill 0.61)
  Top 0.254: v45.55,103.49 44.92,104.12 44.92,125.72 44.29,126.35 41.11,126.35 41.11,125.72 OUT3-4.6
  Bottom 0.254: v45.55,103.49 44.92,103.49 43.65,102.22 IC3.9
N$159  (via drill 0.61)
  Top 0.254: v49.37,111.11 50,111.75 v50,126.35
  Bottom 0.254: v49.37,111.11 44.92,111.11 43.65,109.84 IC3.12 | v50,126.35 45.55,126.35 44.29,125.08 OUT3-4.8
N$160
  Top 0.254: RN1.3 50,93.33 53.18,96.5 53.18,102.86 54.45,104.12 IC4.10 54.45,105.39 51.91,107.94 51.91,121.27 51.27,121.91 OUT3-4.13
N$161  (via drill 0.61)
  Top 0.254: v33.49,121.27 32.86,120.64 32.86,114.92 v32.22,114.28
  Bottom 0.254: 40.48,105.39 40.48,106.03 44.92,106.03 46.19,107.3 IC4.4 | 40.48,105.39 40.48,99.05 46.83,92.69 RN1.4 | v33.49,121.27 46.83,121.27 48.09,122.54 OUT3-4.11 | v32.22,114.28 32.86,113.65 37.3,113.65 39.2,111.75 39.2,108.57 38.57,108.57 37.3,107.3 37.3,105.39 40.48,105.39
N$162  (via drill 0.61)
  Top 0.254: v45.55,100.95 45.55,93.97 44.92,93.33 RN1.5 | OUT3-4.9 46.19,121.91 46.83,121.27 46.83,115.55 IC4.1
  Bottom 0.254: v45.55,100.95 48.73,100.95 51.27,103.49 51.27,114.28 48.09,114.28 IC4.1
N$163
  Top 0.254: IC4.2 48.09,113.02 49.37,114.28 49.37,115.55 48.73,116.19 47.46,116.19 47.46,123.17 46.19,124.44 OUT3-4.10
N$164  (via drill 0.61)
  Top 0.254: v56.35,117.46 56.35,121.91 54.45,123.81 51.27,123.81 51.27,124.44 OUT3-4.14
  Bottom 0.254: v56.35,117.46 56.98,118.09 60.16,118.09 60.16,116.83 60.8,116.19 62.06,116.19 62.06,114.28 61.43,113.65 58.26,113.65 58.26,105.39 55.72,102.86 IC4.9
N$165
  Top 0.254: IC4.12 55.72,110.47 57.62,112.38 57.62,121.91 54.45,125.08 OUT3-4.16
N$166
  Top 0.254: RN1.9 34.76,93.33 32.86,95.23 32.86,113.02 34.12,114.28 IC3.1 34.76,115.55 34.76,120.64 36.03,121.91 OUT3-4.1
N$167
  Top 0.254: RN1.7 39.84,93.33 40.48,93.97 40.48,102.86 41.74,104.12 IC3.10 41.74,105.39 39.2,107.94 39.2,120 41.11,121.91 OUT3-4.5
N$168  (via drill 0.61)
  Top 0.254: v43.02,117.46 42.38,118.09 v42.38,123.81
  Bottom 0.254: v43.02,117.46 41.74,116.19 40.48,116.19 40.48,114.28 41.11,113.65 50.63,113.65 50.63,107.94 48.09,105.39 IC4.5 | v42.38,123.81 46.83,123.81 48.09,125.08 OUT3-4.12
N$169
  Top 0.254: OUT3-4.15 53.81,121.91 52.54,120.64 52.54,114.92 54.45,113.02 IC4.13
  Bottom 0.254: RN1.2 52.54,93.33 52.54,112.38 53.81,112.38 IC4.13
N$170  (via drill 0.61)
  Top 0.254: v60.16,80.63 60.16,69.2 62.06,67.3 IC7.4 | RN2.8 66.51,55.23 66.51,81.27 OUT7-8.3
  Bottom 0.254: v60.16,80.63 64.6,80.63 65.88,81.9 OUT7-8.3
N$171
  Top 0.254: RN2.6 71.59,55.23 72.22,55.87 72.22,64.75 71.59,65.39 68.41,65.39 68.41,69.83 69.68,71.11 IC7.13 70.95,72.38 72.22,73.64 72.22,80.63 71.59,81.27 OUT7-8.7
N$172
  Top 0.254: IC7.2 62.06,72.38 60.8,73.64 60.8,79.36 62.7,81.27 62.7,82.53 63.97,83.8 OUT7-8.2
N$173  (via drill 0.61)
  Top 0.254: v58.89,65.39 v58.89,83.17
  Bottom 0.254: v58.89,65.39 60.16,65.39 61.43,64.12 IC7.5 | v58.89,83.17 64.6,83.17 65.88,84.44 OUT7-8.4
N$174
  Bottom 0.254: IC7.9 69.68,62.21 64.6,67.3 64.6,73.01 53.81,73.01 52.54,74.28 46.19,74.28 44.92,75.55 44.92,79.36 65.88,79.36 67.78,81.27 67.78,84.44 68.41,84.44 OUT7-8.6
N$175
  Top 0.254: IC7.12 70.95,69.83 72.86,71.74 72.86,82.53 71.59,83.8 OUT7-8.8
N$176  (via drill 0.61)
  Top 0.254: RN2.3 79.21,55.23 v79.21,64.12 79.21,81.27 OUT7-8.13
  Bottom 0.254: v79.21,64.12 81.75,64.12 IC8.10
N$177  (via drill 0.61)
  Top 0.254: RN2.4 76.67,55.23 76.67,56.5 v77.3,57.13 77.94,57.77 77.94,80 76.67,81.27 OUT7-8.11
  Bottom 0.254: v77.3,57.13 77.3,64.75 76.03,66.03 IC8.4
N$178
  Top 0.254: 73.49,74.28 73.49,81.9 OUT7-8.9 | 73.49,74.28 73.49,55.87 74.13,55.23 RN2.5 | 73.49,74.28 74.13,74.28 IC8.1
N$179
  Bottom 0.254: IC8.2 76.67,71.74 77.3,72.38 81.11,72.38 81.75,73.01 84.29,73.01 84.92,73.64 84.92,85.71 76.03,85.71 74.77,84.44 OUT7-8.10
N$180  (via drill 0.61)
  Top 0.254: v55.08,52.05 55.72,52.69 v55.72,77.45
  Bottom 0.254: v55.08,52.05 85.56,52.05 85.56,59.04 83.65,60.95 IC8.9 | v55.72,77.45 56.98,78.72 75.4,78.72 77.94,81.27 77.94,84.44 78.57,84.44 OUT7-8.14
N$181
  Bottom 0.254: IC8.12 81.75,69.2 80.48,67.93 74.13,67.93 73.49,68.56 73.49,73.01 79.21,73.01 81.75,75.55 82.38,75.55 83.02,76.19 83.02,83.8 81.75,83.8 OUT7-8.16
N$182
  Top 0.254: 62.7,80 62.7,74.92 IC7.1 | 62.7,80 63.97,81.27 OUT7-8.1 | 62.7,80 65.24,77.45 65.24,56.5 63.97,55.23 RN2.9
N$183
  Top 0.254: 69.05,62.85 69.68,63.48 IC7.10 | 69.05,62.85 68.41,62.21 68.41,55.87 69.05,55.23 RN2.7 | 69.05,62.85 67.78,64.12 67.78,80 69.05,81.27 OUT7-8.5
N$184  (via drill 0.61)
  Top 0.254: v70.95,76.82 70.32,77.45 v70.32,83.17
  Bottom 0.254: v70.95,76.82 69.68,75.55 68.41,75.55 68.41,73.64 69.05,73.01 72.22,73.01 72.22,67.3 74.77,64.75 IC8.5 | v70.32,83.17 74.77,83.17 76.03,84.44 OUT7-8.12
N$185
  Top 0.254: 80.48,71.11 80.48,59.04 81.75,57.77 81.75,55.23 RN2.2 | 80.48,71.11 81.11,71.74 81.75,71.74 IC8.13 | 80.48,71.11 80.48,80 81.75,81.27 OUT7-8.15
OA1  (via drill 0.61)
  Top 0.254: 6.82,79.36 5.55,78.09 A1-K1.18 | 6.82,79.36 6.82,81.9 JP1.1 6.82,84.44 6.82,87.61 5.55,88.89 5.55,99.68 7.46,101.58 7.46,107.94 8.73,109.2 IC1.3 | v10.63,50.15 10.63,24.11 11.9,22.84 11.9,7.61 10.63,6.33 IN1-2.1 | v8.09,52.69 8.09,66.66 6.82,67.93 6.82,79.36
  Bottom 0.254: v10.63,50.15 10.63,52.69 v8.09,52.69
OB1  (via drill 0.61)
  Top 0.254: 8.09,78.09 9.36,79.36 9.36,81.9 JP1.2 | 8.09,78.09 A1-K1.17 8.09,78.09 | 8.09,78.09 8.09,97.14 7.46,97.78 7.46,100.31 8.73,101.58 IC1.6 | v7.46,4.43 6.82,5.07 v6.82,24.75
  Bottom 0.254: v7.46,4.43 11.27,4.43 12.54,5.7 IN1-2.3 | v6.82,24.75 1.74,29.83 1.74,78.72 6.18,78.72 7.46,77.45 A1-K1.17
OB2
  Top 0.254: A2-K2.17 41.11,38.72 42.38,39.99 42.38,42.53 JP2.2
OC
  Bottom 0.254: 10,32.37 8.73,32.37 7.46,33.64 OC.1 | 10,32.37 20.79,32.37 20.79,26.02 20.16,25.38 16.35,25.38 15.08,26.66 IC9.8 | 5.55,29.83 7.46,29.83 10,32.37 | 5.55,29.83 4.92,29.83 4.92,36.18 6.18,37.45 16.98,37.45 18.89,35.55 IC9.5 | 5.55,29.83 5.55,27.93 13.81,19.67 30.95,19.67 36.03,14.59 39.84,14.59 39.84,5.07 40.48,4.43 59.52,4.43 60.8,5.7 IN5-6.1
OC1  (via drill 0.61)
  Top 0.254: A1-K1.16 10.63,78.09 11.9,79.36 11.9,81.9 JP1.3 11.9,84.44 18.25,90.79 18.25,98.41 17.62,99.05 IC1.8 | v13.17,41.26 13.17,26.02 14.44,24.75 14.44,7.61 15.71,6.33 IN1-2.5
  Bottom 0.254: v13.17,41.26 6.18,48.24 4.28,48.24 2.38,50.15 2.38,74.92 8.73,74.92 10,76.19 A1-K1.16
OD1  (via drill 0.61)
  Top 0.254: A1-K1.15 13.17,78.09 14.44,79.36 14.44,81.9 JP1.4 | v2.38,7.61 1.74,8.24 1.74,85.08 v2.38,85.71
  Bottom 0.254: 3.01,85.71 3.01,98.41 8.09,103.49 11.9,103.49 15.71,107.3 IC1.11 | 3.01,85.71 13.17,85.71 14.44,84.44 JP1.4 | v2.38,7.61 3.65,7.61 4.28,8.24 6.82,8.24 8.09,6.97 16.35,6.97 17.62,5.7 IN1-2.7 | v2.38,85.71 3.01,85.71
OD2
  Top 0.254: JP2.4 47.46,42.53 47.46,39.99 46.19,38.72 A2-K2.15 46.19,36.18 46.19,35.55 | 46.19,35.55 49.37,35.55 50,36.18 50,38.72 51.27,39.99 51.27,45.7 53.81,48.24 53.81,83.8 61.43,91.42 61.43,97.14 62.06,97.78 62.06,100.31 60.8,101.58 IC5.6 | 46.19,35.55 41.74,35.55 37.3,31.1 37.3,7.61 38.57,6.33 IN3-4.3
OE1  (via drill 0.61)
  Top 0.254: A1-K1.14 15.71,78.09 16.98,79.36 16.98,81.9 JP1.5 | v3.01,8.88 2.38,9.51 2.38,83.8 v5.55,86.98
  Bottom 0.254: IC2.3 21.43,109.2 18.25,106.03 15.71,106.03 10.63,100.95 8.09,100.95 5.55,98.41 v5.55,86.98 5.55,86.34 15.08,86.34 16.98,84.44 JP1.5 | v3.01,8.88 9.36,8.88 10,8.24 IN1-2.2
OE2  (via drill 0.61)
  Top 0.254: A2-K2.14 48.73,38.72 50,39.99 50,42.53 JP2.5 50.63,44.44 50.63,52.05 53.18,54.59 53.18,85.08 v53.81,85.71 | v69.05,86.34 69.05,98.41 68.41,99.05 IC5.8 | v38.57,27.29 38.57,13.96 39.84,12.68 39.84,7.61 41.11,6.33 IN3-4.5
  Bottom 0.254: v69.05,86.34 68.41,85.71 v53.81,85.71 | v38.57,27.29 39.84,28.56 39.84,33.64 44.92,33.64 48.09,36.81 A2-K2.14
OF1  (via drill 0.61)
  Top 0.254: A1-K1.13 18.25,78.09 19.52,79.36 19.52,81.9 JP1.6 19.52,84.44 23.33,88.25 23.33,97.14 23.96,97.78 23.96,100.31 22.7,101.58 IC2.6 | v3.65,10.14 3.01,10.78 3.01,39.35 4.28,40.62 4.28,48.24 3.01,49.52 3.01,77.45 v5.55,80
  Bottom 0.254: v3.65,10.14 10.63,10.14 12.54,8.24 IN1-2.4 | v5.55,80 6.18,79.36 15.71,79.36 17.62,77.45 A1-K1.13
OF2  (via drill 0.61)
  Top 0.254: A2-K2.13 51.27,38.72 52.54,39.99 52.54,42.53 JP2.6 | v86.19,99.05 v86.19,62.21 86.19,27.93 84.92,26.66 84.92,6.97 53.18,6.97 52.54,6.33 52.54,4.43 45.55,4.43 44.29,5.7 IN3-4.7
  Bottom 0.254: v86.19,99.05 85.56,98.41 76.67,98.41 74.13,100.95 70.32,100.95 70.32,104.76 68.41,106.67 IC5.11 | v86.19,62.21 86.19,51.42 58.89,51.42 52.54,45.07 JP2.6
OH1  (via drill 0.61)
  Top 0.254: JP1.7 22.06,81.9 22.06,79.36 20.79,78.09 A1-K1.12 20.16,76.19 14.44,70.47 14.44,67.93 15.71,66.66 15.71,8.88 IN1-2.6 | v28.41,88.25 28.41,98.41 29.05,99.05 IC2.8
  Bottom 0.254: v28.41,88.25 25.87,85.71 23.33,85.71 22.06,84.44 JP1.7
OH2  (via drill 0.61)
  Top 0.254: A2-K2.12 53.81,38.72 55.08,39.99 55.08,42.53 JP2.7 | v82.38,108.57 84.92,106.03 84.92,76.19 85.56,75.55 85.56,68.56 v84.92,67.93 | v62.7,50.15 v62.7,55.87 | v35.4,38.09 36.03,37.45 36.03,13.32 34.76,12.05 34.76,8.88 35.4,8.24 IN3-4.2
  Bottom 0.254: v82.38,108.57 75.4,108.57 74.13,109.84 IC6.3 | v84.92,67.93 84.92,62.85 81.75,62.85 78.57,59.67 78.57,55.87 v62.7,55.87 | v62.7,50.15 60.16,47.61 56.98,47.61 55.08,45.7 55.08,45.07 JP2.7 | v35.4,38.09 36.66,39.35 51.91,39.35 53.18,38.09 A2-K2.12
OJ1  (via drill 0.61)
  Top 0.254: JP1.8 24.6,81.9 24.6,79.36 23.33,78.09 A1-K1.11 23.33,75.55 23.33,71.11 25.23,71.11 28.41,74.28 | 28.41,74.28 28.41,85.08 30.95,87.61 30.95,93.33 32.22,94.6 32.22,104.76 30.32,106.67 IC2.11 | v18.25,50.15 18.25,8.88 IN1-2.8 | v28.41,55.23 28.41,74.28
  Bottom 0.254: v18.25,50.15 18.25,55.23 v28.41,55.23
OJ2  (via drill 0.61)
  Top 0.254: A2-K2.11 56.35,38.72 57.62,39.99 57.62,42.53 JP2.8 | v83.65,100.95 84.29,100.31 84.29,75.55 84.92,74.92 84.92,71.11 84.29,70.47 81.11,70.47 81.11,60.95 81.75,60.31 84.92,60.31 84.92,57.13 83.02,55.23 83.02,46.98 81.75,45.7 v81.75,41.89 | v34.76,26.02 34.76,13.32 34.12,12.68 34.12,4.43 39.2,4.43 39.84,5.07 39.84,6.33 38.57,7.61 IN3-4.4
  Bottom 0.254: v83.65,100.95 75.4,100.95 74.13,102.22 IC6.6 | v81.75,41.89 81.11,41.26 58.89,41.26 57.62,42.53 JP2.8 | v34.76,26.02 52.54,26.02 55.08,28.56 55.08,36.81 55.72,36.81 A2-K2.11
OK1  (via drill 0.61)
  Top 0.254: 25.87,78.09 27.14,79.36 27.14,81.9 JP1.9 | A1-K1.10 25.87,78.09 | 25.87,78.09 v25.87,97.78 | A1-K1.10 25.87,78.09 | v23.33,66.66 23.33,24.11 21.43,22.21 21.43,15.86 22.06,15.22 22.06,7.61 20.79,6.33 IN1-2.9 | v24.6,72.38 25.87,73.64 25.87,75.55 A1-K1.10
  Bottom 0.254: v25.87,97.78 36.66,97.78 36.66,107.94 35.4,109.2 IC3.3 | v23.33,66.66 24.6,67.93 v24.6,72.38
OK2  (via drill 0.61)
  Top 0.254: JP2.9 60.16,42.53 60.16,39.99 58.89,38.72 A2-K2.10 58.89,36.18 58.89,34.91 | v81.75,86.98 81.11,87.61 81.11,88.89 81.75,89.52 81.75,98.41 81.11,99.05 IC6.8 | v65.88,90.16 65.88,86.98 67.78,85.08 67.78,81.27 67.14,80.63 67.14,55.87 67.78,55.23 67.78,46.98 69.05,45.7 69.05,39.99 70.32,38.72 70.32,36.18 69.05,34.91 58.89,34.91 | v39.84,15.86 39.84,13.96 40.48,13.32 40.48,9.51 41.11,8.88 IN3-4.6 | v58.89,19.67 58.89,27.29 57.62,28.56 57.62,33.64 58.89,34.91
  Bottom 0.254: v81.75,86.98 78.57,90.16 v65.88,90.16 | v39.84,15.86 39.84,19.67 v58.89,19.67
OL1  (via drill 0.61)
  Top 0.254: L1-V1.18 30.95,78.09 29.68,79.36 29.68,81.9 JP1.10 29.68,84.44 36.03,90.79 36.03,93.33 36.66,93.97 36.66,100.31 35.4,101.58 IC3.6 | v28.41,37.45 28.41,16.5 24.6,12.68 24.6,7.61 23.33,6.33 IN1-2.11 | v22.06,43.8 22.06,49.52 20.79,50.78 v20.79,66.66
  Bottom 0.254: v28.41,37.45 v22.06,43.8 | v20.79,66.66 22.06,67.93 22.06,73.64 27.78,73.64 30.32,76.19 L1-V1.18
OL2  (via drill 0.61)
  Top 0.254: L2-V2.18 63.97,38.72 62.7,39.99 62.7,42.53 JP2.10 | v82.38,88.25 82.38,105.39 81.11,106.67 IC6.11 | v41.11,20.94 41.11,19.04 42.38,17.77 42.38,10.14 43.65,8.88 IN3-4.8
  Bottom 0.254: v82.38,88.25 84.29,86.34 85.56,86.34 88.1,83.8 88.1,39.99 66.51,39.99 64.6,38.09 L2-V2.18 63.34,36.81 61.43,36.81 61.43,21.57 60.8,20.94 v41.11,20.94
OM1  (via drill 0.61)
  Top 0.254: L1-V1.17 33.49,78.09 32.22,79.36 32.22,81.9 JP1.11 | v41.11,86.34 41.11,98.41 41.74,99.05 IC3.8 | v24.6,14.59 25.87,15.86 v25.87,41.89
  Bottom 0.254: v41.11,86.34 40.48,85.71 33.49,85.71 32.22,84.44 JP1.11 | v24.6,14.59 24.6,7.61 25.87,6.33 IN1-2.13 | v25.87,41.89 31.59,47.61 48.09,47.61 52.54,52.05 52.54,73.01 36.03,73.01 33.49,75.55 L1-V1.17
OM2  (via drill 0.61)
  Top 0.254: L2-V2.17 66.51,38.72 65.24,39.99 65.24,42.53 JP2.11 | v60.16,66.66 60.16,60.31 57.62,57.77 57.62,50.78 59.52,48.88 59.52,46.34 v58.89,45.7
  Bottom 0.254: v60.16,66.66 62.06,68.56 IC7.3 | v58.89,45.7 59.52,46.34 63.97,46.34 65.24,45.07 JP2.11 | IN3-4.9 46.19,6.33 44.92,7.61 44.92,13.32 67.14,13.32 67.78,13.96 67.78,20.94 68.41,20.94 69.05,21.57 69.05,27.93 69.68,27.93 70.32,28.56 70.32,39.35 68.41,39.35 67.14,38.09 L2-V2.17
ON1  (via drill 0.61)
  Top 0.254: L1-V1.16 36.03,78.09 34.76,79.36 34.76,81.9 JP1.12 | v41.11,120 39.84,118.73 39.84,109.84 41.74,107.94 IC3.11 | v58.89,116.83 v58.89,120 | 63.97,91.42 63.97,86.34 60.8,83.17 v60.8,81.9 | 63.97,91.42 v63.97,100.95 | v87.46,12.05 v87.46,86.34 | v66.51,91.42 63.97,91.42
  Bottom 0.254: v58.89,120 v41.11,120 | v58.89,116.83 56.98,114.92 56.98,106.03 53.81,106.03 53.18,105.39 53.18,100.95 v63.97,100.95 | v60.8,81.9 51.91,81.9 50.63,80.63 36.03,80.63 34.76,81.9 JP1.12 | v87.46,12.05 79.21,3.79 30.95,3.79 29.05,5.7 IN1-2.15 | v87.46,86.34 82.38,91.42 v66.51,91.42
ON2  (via drill 0.61)
  Top 0.254: JP2.12 67.78,42.53 67.78,39.99 69.05,38.72 L2-V2.16 68.41,36.81 68.41,35.55 63.34,35.55 61.43,37.45 61.43,45.7 60.16,46.98 60.16,59.04 62.06,60.95 IC7.6 | v52.54,15.86 52.54,13.96 47.46,8.88 47.46,7.61 48.73,6.33 IN3-4.11
  Bottom 0.254: v52.54,15.86 52.54,18.4 60.8,18.4 63.97,21.57 63.97,27.93 64.6,27.93 65.24,28.56 65.24,35.55 67.14,35.55 68.41,36.81 L2-V2.16
OP1  (via drill 0.61)
  Top 0.254: 38.57,78.09 37.3,79.36 37.3,81.9 JP1.13 | L1-V1.15 38.57,78.09 | 38.57,78.09 v38.57,106.67 | L1-V1.15 38.57,78.09 | v20.79,46.34 20.79,8.88 IN1-2.10 | v39.2,48.88 41.11,50.78 v41.11,66.66 | v39.84,71.74 38.57,73.01 38.57,75.55 L1-V1.15
  Bottom 0.254: v38.57,106.67 40.48,108.57 44.92,108.57 46.19,109.84 IC4.3 | v20.79,46.34 23.33,48.88 v39.2,48.88 | v41.11,66.66 39.84,67.93 v39.84,71.74
OP2
  Top 0.254: IC7.8 70.32,58.41 70.32,45.07 JP2.13 70.32,42.53 70.32,39.99 71.59,38.72 L2-V2.15
  Bottom 0.254: IN3-4.13 51.27,6.33 50,7.61 50,11.41 80.48,11.41 85.56,16.5 85.56,34.91 74.13,34.91 72.22,36.81 L2-V2.15
OR1  (via drill 0.61)
  Top 0.254: JP1.14 39.84,81.9 39.84,79.36 41.11,78.09 L1-V1.14 41.11,75.55 41.11,74.92 46.83,74.92 47.46,75.55 47.46,78.09 46.19,79.36 46.19,85.08 48.73,87.61 48.73,93.33 49.37,93.97 49.37,100.31 48.09,101.58 IC4.6 | v4.28,11.41 4.92,12.05 v4.92,49.52
  Bottom 0.254: v4.28,11.41 19.52,11.41 22.7,8.24 IN1-2.12 | v4.92,49.52 4.28,50.15 3.65,50.15 3.01,50.78 3.01,74.28 25.87,74.28 30.32,78.72 39.2,78.72 40.48,77.45 L1-V1.14
OR2
  Top 0.254: L2-V2.14 74.13,38.72 72.86,39.99 72.86,42.53 JP2.14 72.86,45.07 72.86,65.39 71.59,66.66 IC7.11
  Bottom 0.254: IN3-4.15 54.45,5.7 58.26,9.51 81.11,9.51 86.83,15.22 86.83,39.35 76.03,39.35 74.77,38.09 L2-V2.14
OS1  (via drill 0.61)
  Top 0.254: L1-V1.13 43.65,78.09 42.38,79.36 42.38,81.9 JP1.15 42.38,84.44 42.38,86.34 v44.92,88.89 | v36.03,11.41 36.66,12.05 36.66,50.15 36.03,50.78 36.03,52.05 36.66,52.69 38.57,52.69 38.57,54.59 36.66,56.5 36.66,60.31 36.03,60.95 36.03,66.66 37.3,67.93 v37.3,74.28
  Bottom 0.254: v44.92,88.89 58.89,88.89 58.89,97.14 56.35,99.68 IC4.8 | v36.03,11.41 29.68,11.41 26.51,8.24 IN1-2.14 | v37.3,74.28 37.94,74.92 41.74,74.92 43.02,76.19 L1-V1.13
OS2  (via drill 0.61)
  Top 0.254: 75.4,39.99 76.67,38.72 L2-V2.13 | 75.4,39.99 75.4,42.53 JP2.15 | v74.13,20.94 74.13,27.29 75.4,28.56 75.4,39.99
  Bottom 0.254: IC8.3 76.67,69.2 77.94,70.47 84.29,70.47 87.46,67.3 87.46,46.34 76.67,46.34 75.4,45.07 JP2.15 | v74.13,20.94 72.86,20.94 72.86,13.96 71.59,12.68 50,12.68 46.19,8.88 IN3-4.10
OT2  (via drill 0.61)
  Top 0.254: JP2.16 77.94,42.53 77.94,39.99 79.21,38.72 L2-V2.12 79.21,36.18 77.94,34.91 77.94,28.56 76.67,27.29 76.67,19.04 75.4,17.77 75.4,16.5 74.77,15.86 55.08,15.86 | v58.26,60.31 56.35,58.41 56.35,39.99 55.08,38.72 55.08,28.56 56.35,27.29 56.35,19.04 55.08,17.77 55.08,15.86 | 55.08,15.86 55.08,13.96 49.37,8.24 IN3-4.12
  Bottom 0.254: v58.26,60.31 72.86,60.31 74.13,61.58 IC8.6
OU1  (via drill 0.61)
  Top 0.254: JP1.17 47.46,81.9 47.46,79.36 48.73,78.09 L1-V1.11 48.73,75.55 47.46,74.28 47.46,67.93 46.19,66.66 46.19,50.78 v41.74,46.34 | v52.54,86.34 56.35,90.16 56.35,97.14 56.98,97.78 56.98,105.39 55.72,106.67 IC4.11 | v34.12,46.34 34.12,27.29 33.49,26.66 33.49,25.38 34.12,24.75 34.12,13.96 33.49,13.32 33.49,8.24 29.05,8.24 IN1-2.16
  Bottom 0.254: v52.54,86.34 51.91,85.71 48.73,85.71 47.46,84.44 JP1.17 | v34.12,46.34 v41.74,46.34
OU2  (via drill 0.61)
  Top 0.254: L2-V2.11 81.75,38.72 80.48,39.99 80.48,42.53 JP2.17 80.48,45.07 v80.48,56.5
  Bottom 0.254: v80.48,56.5 82.38,58.41 IC8.8 | IN3-4.14 51.91,8.24 53.81,10.14 80.48,10.14 86.19,15.86 86.19,35.55 83.65,35.55 82.38,36.81 L2-V2.11
OV1  (via drill 0.61)
  Top 0.254: 50,79.36 51.27,78.09 L1-V1.10 | 50,79.36 50,81.9 JP1.18 50,84.44 v50,86.98 | v65.24,106.03 65.88,105.39 65.88,97.78 66.51,97.14 v66.51,93.97 | v32.22,10.14 32.86,10.78 32.86,13.96 33.49,14.59 33.49,24.11 32.86,24.75 32.86,27.29 33.49,27.93 33.49,45.07 32.86,45.7 32.86,48.24 v30.95,50.15 | v48.73,50.15 48.73,66.66 50,67.93 50,79.36
  Bottom 0.254: v65.24,106.03 61.43,109.84 IC5.3 | v66.51,93.97 60.8,88.25 51.27,88.25 v50,86.98 | v32.22,10.14 36.03,6.33 IN3-4.1 | v30.95,50.15 v48.73,50.15
OV2
  Top 0.254: IC8.11 83.65,66.03 84.92,64.75 84.92,61.58 85.56,60.95 85.56,47.61 83.02,45.07 JP2.18 83.02,42.53 83.02,39.99 84.29,38.72 L2-V2.10 84.29,36.18 85.56,34.91 85.56,28.56 84.29,27.29 84.29,13.32 64.6,13.32 60.16,8.88 60.16,8.24 54.45,8.24 IN3-4.16
P1
  Top 0.254: L1-V1.4 38.57,67.93 37.3,66.66 37.3,64.12 JP3.13 37.3,61.58 37.3,57.13 39.84,54.59 SIDE1.30
P2
  Top 0.254: L2-V2.4 71.59,28.56 70.32,27.29 70.32,24.75 JP4.13 70.32,22.21 70.32,19.04 69.05,17.77 SIDE2.24
R1  (via drill 0.61)
  Top 0.254: L1-V1.5 40.48,68.56 39.84,67.93 39.84,64.12 JP3.14 | v34.76,56.5 34.76,54.59 SIDE1.26
  Bottom 0.254: v34.76,56.5 39.84,61.58 JP3.14
R2
  Top 0.254: L2-V2.5 74.13,28.56 72.86,27.29 72.86,24.75 JP4.14 72.86,22.21 72.86,19.04 71.59,17.77 SIDE2.26
S1
  Top 0.254: L1-V1.6 43.65,67.93 42.38,66.66 42.38,64.12 JP3.15 42.38,61.58 42.38,54.59 SIDE1.32
S2
  Top 0.254: L2-V2.6 76.67,28.56 75.4,27.29 75.4,24.75 JP4.15 75.4,22.21 75.4,19.04 74.13,17.77 SIDE2.28
T1
  Top 0.254: L1-V1.7 46.19,67.93 44.92,66.66 44.92,64.12 JP3.16 44.92,61.58 44.92,54.59 SIDE1.34
T2
  Top 0.254: L2-V2.7 79.21,28.56 77.94,27.29 77.94,24.75 JP4.16 77.94,22.21 77.94,19.04 76.67,17.77 SIDE2.30
U1
  Top 0.254: L1-V1.8 48.73,67.93 47.46,66.66 47.46,64.12 JP3.17
  Bottom 0.254: SIDE1.4 7.46,53.96 10,56.5 32.86,56.5 34.12,55.23 41.11,55.23 47.46,61.58 JP3.17
U2
  Top 0.254: L2-V2.8 81.75,28.56 80.48,27.29 80.48,24.75 JP4.17 80.48,22.21 80.48,19.04 81.75,17.77 SIDE2.34
V1
  Top 0.254: L1-V1.9 51.27,67.93 50,66.66 50,64.12 JP3.18
  Bottom 0.254: SIDE1.2 4.28,54.59 4.28,65.39 48.73,65.39 50,64.12 JP3.18
V2
  Top 0.254: L2-V2.9 84.29,28.56 83.02,27.29 83.02,24.75 JP4.18
  Bottom 0.254: SIDE2.32 79.21,17.77 83.02,21.57 83.02,22.21 JP4.18
VCC  (via drill 0.61)
  Top 0.305: BYP6.1 79.21,116.83 79.21,116.19 79.84,115.55 IC6.14 81.11,114.28 82.38,113.02 82.38,111.75 81.75,111.11 78.57,111.11 78.57,99.05 80.48,97.14 RN4.1 80.48,94.6 80.48,83.8 81.11,83.17 83.02,83.17 83.02,74.92 IC8.14 82.38,74.92 82.38,75.55 81.75,76.19 BYP8.1 | BYP7.1 69.05,76.19 69.68,75.55 69.68,74.92 IC7.14 | IC1.14 16.35,115.55 15.71,116.19 15.71,116.83 BYP1.1 | BYP2.1 28.41,116.83 28.41,116.19 29.05,115.55 IC2.14 29.05,114.28 27.78,113.02 27.78,103.49 30.95,103.49 31.59,102.86 31.59,99.05 29.68,97.14 RN3.1 | IC5.14 67.14,115.55 66.51,116.19 66.51,116.83 BYP5.1 | IC3.14 41.74,115.55 41.11,116.19 41.11,116.83 BYP3.1 | IC4.14 54.45,115.55 53.81,116.19 53.81,116.83 BYP4.1 53.81,118.09 53.81,120 v55.08,121.27 | IC9.1 29.68,33.64 29.68,28.56 IC9.14 | POWER.2 32.22,17.13 32.22,20.3 POWER2.2 32.22,22.84 32.22,27.93 BYP9.1 | A2-K2.18 38.57,38.72 39.84,39.99 39.84,42.53 JP2.1 | v84.29,50.15 84.29,52.69 RN2.1 | v48.73,41.26 48.73,45.7 50,46.98 50,52.69 52.54,55.23 52.54,78.09 51.27,79.36 51.27,86.98 55.08,90.79 RN1.1
  Bottom 0.305: IC7.14 71.59,74.28 72.86,75.55 79.84,75.55 81.11,76.82 BYP8.1 | RN3.1 29.68,94.6 30.95,93.33 30.95,90.16 53.18,90.16 54.45,91.42 RN1.1 | IC1.14 18.25,114.92 19.52,116.19 24.6,116.19 25.87,117.46 27.78,117.46 BYP2.1 | IC3.14 43.65,114.92 44.92,116.19 51.91,116.19 53.18,117.46 BYP4.1 | v55.08,121.27 62.06,121.27 65.88,117.46 BYP5.1 | IC2.14 30.95,114.92 32.22,116.19 39.2,116.19 40.48,117.46 BYP3.1 | IC6.14 81.11,114.28 83.65,111.75 83.65,105.39 81.75,103.49 71.59,103.49 70.95,104.12 70.95,108.57 66.51,108.57 65.88,109.2 65.88,114.92 66.51,114.92 IC5.14 | IC9.3 25.23,34.27 26.51,34.27 IC9.2 27.78,34.27 29.05,34.27 IC9.1 30.32,35.55 31.59,36.81 37.94,36.81 A2-K2.18 | IC9.13 27.78,26.66 29.05,26.66 IC9.14 30.32,27.93 30.95,27.93 31.59,28.56 BYP9.1 | BYP10.1 8.73,15.86 10.63,17.77 30.32,17.77 31.59,16.5 POWER.2 | v84.29,50.15 81.11,46.98 57.62,46.98 56.35,45.7 56.35,41.26 v48.73,41.26 41.11,41.26 39.84,42.53 JP2.1

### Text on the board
Top: Component Side | PA8PDP/VRS
Bottom: Solder Side
tPlace: 16 | 16 | 16 | 1 | 1 | 1 | 1 | 1 | 1 | 16 | 1 | 34 | 1 | 1 | 34 | 1 | 16 | 16 | 16 | 1 | 1 | 1
tNames: OUT3-4 | OUT5-6 | IC1 | IC2 | IC3 | IC4 | IC5 | IC6 | RN3 | RN4 | RN1 | OUT7-8 | JP1 | A1-K1 | L1-V1 | IC7 | IC8 | JP3 | SIDE1 | RN2 | JP2 | A2-K2 | L2-V2 | IC9 | C1 | BYP9 | JP4 | R1 | SIDE2
tValues: 74LS125N | 74LS125N | 74LS125N | 74LS125N | 74LS125N | 74LS125N | A1-K1 | L1-V1 | 74LS125N | 74LS125N | FlipChip Tester - Rev. 2 | A2-K2 | L2-V2 | 74LS10N | 0.1uf | 0.1uf | 1K | - | + | + | -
